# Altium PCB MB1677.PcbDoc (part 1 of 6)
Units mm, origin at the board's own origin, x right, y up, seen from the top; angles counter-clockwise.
Board outline 78 x 105 mm, 6 copper layers (Top Layer, Signal Layer 1, Signal Layer 2, Signal Layer 3, Signal Layer 4, Bottom Layer), stack 1.574 mm thick; 404 components, 325 nets, 1691 pads, 961 vias.
Unrouted connection lines stored in the file: 9.
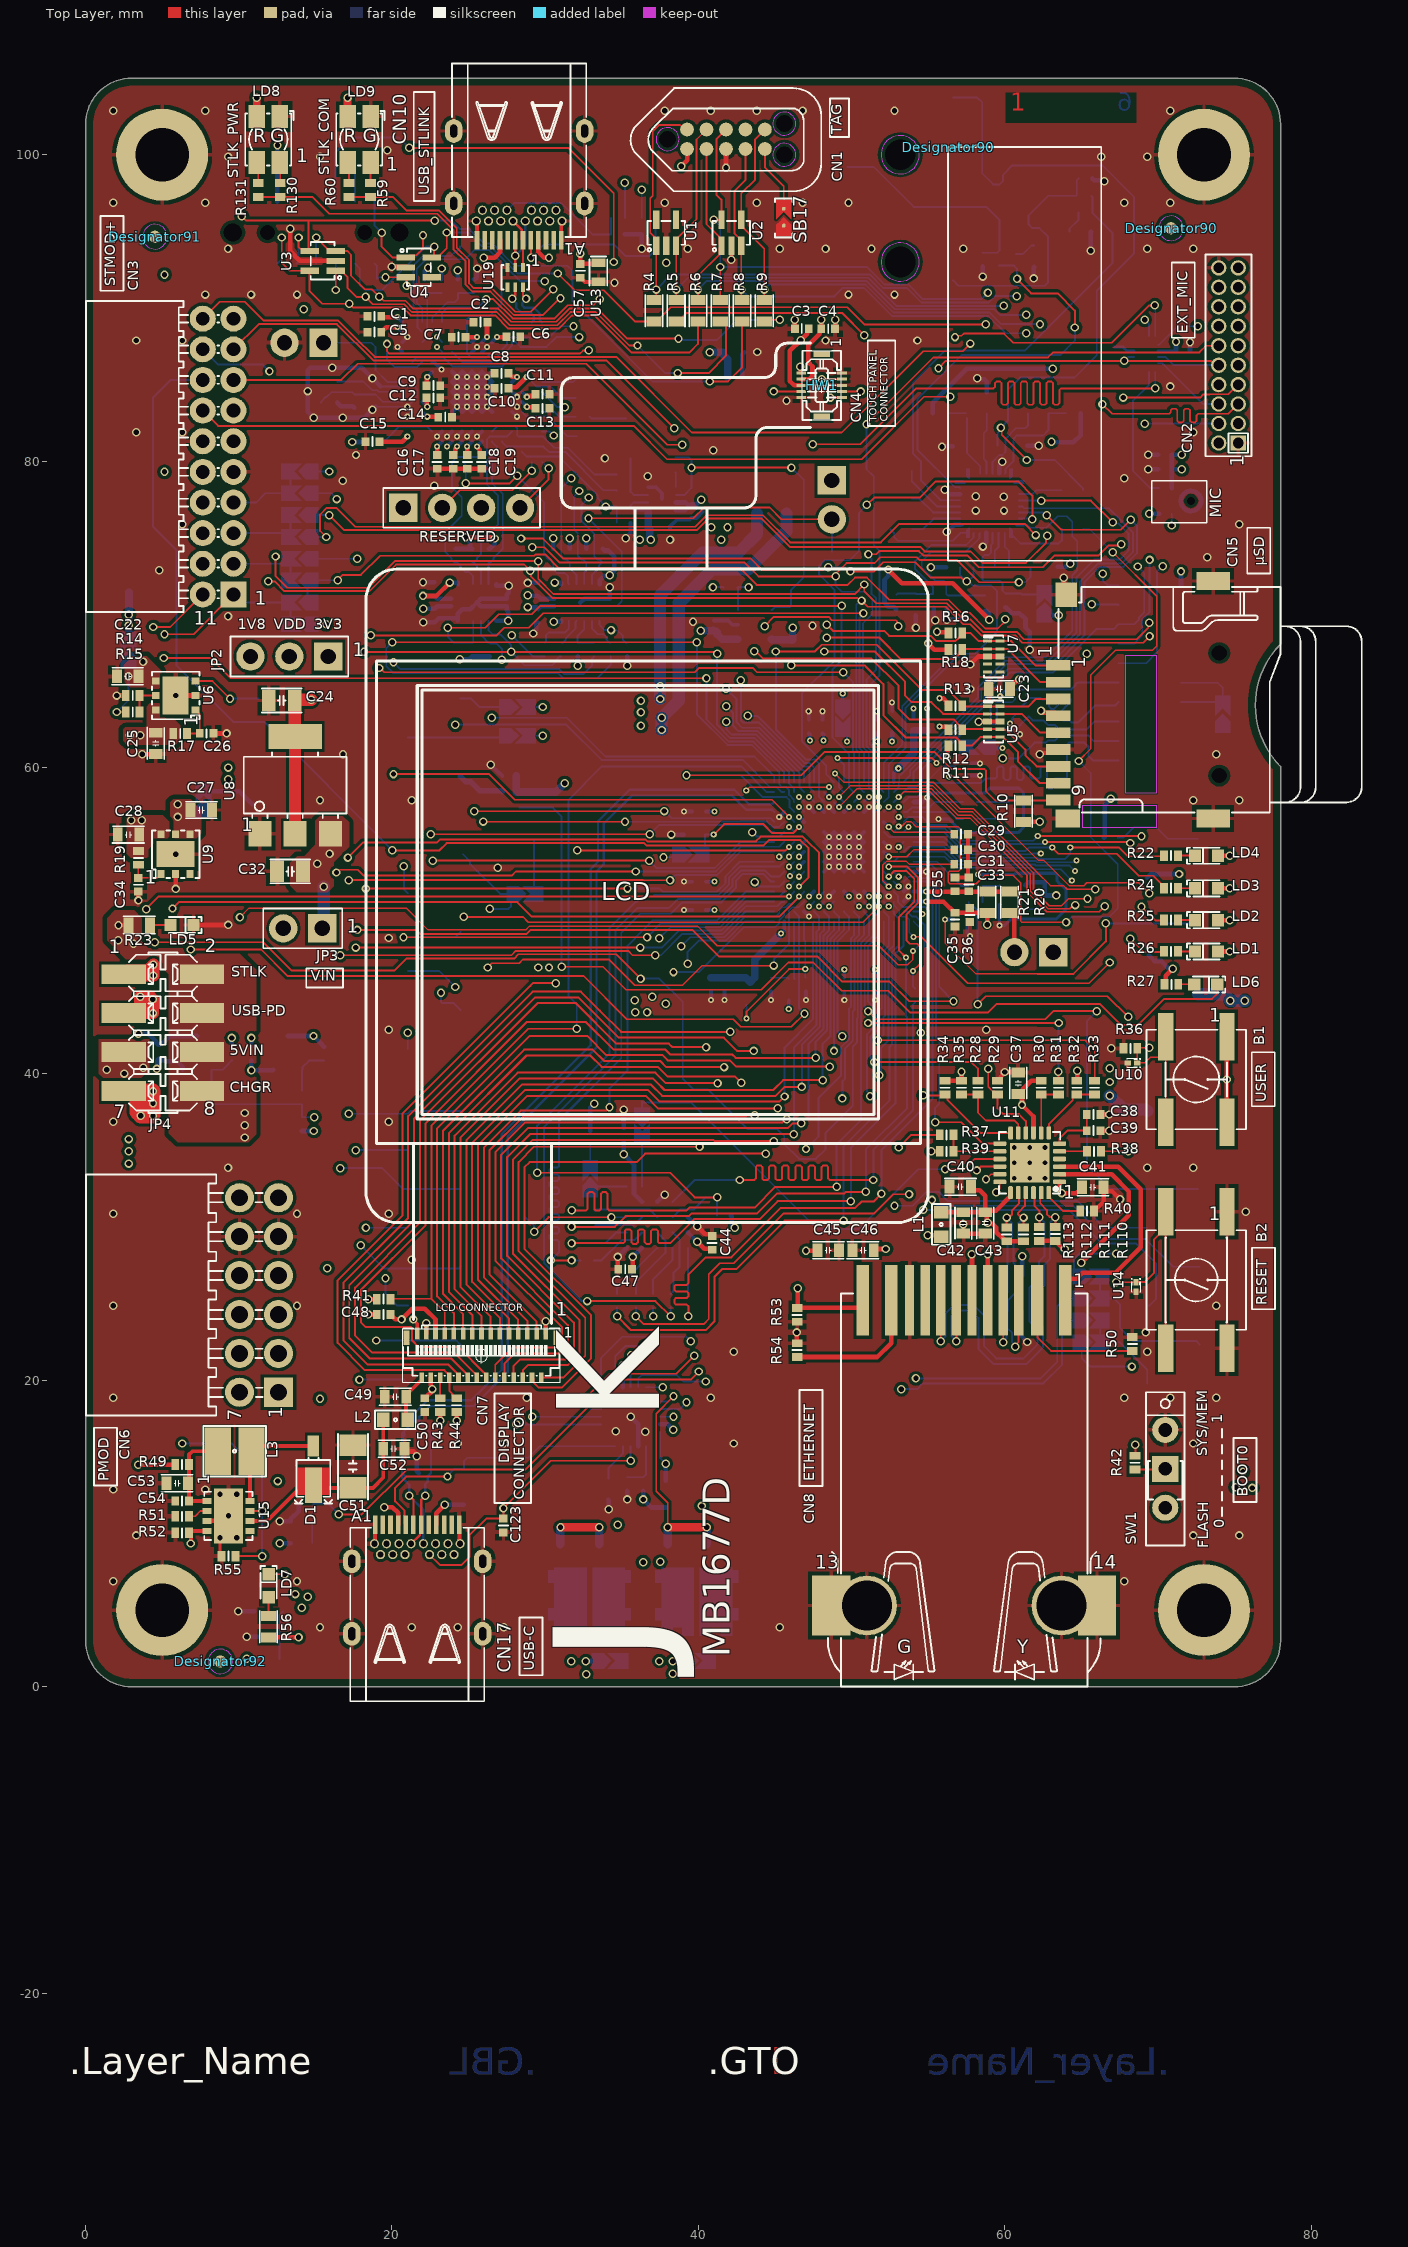
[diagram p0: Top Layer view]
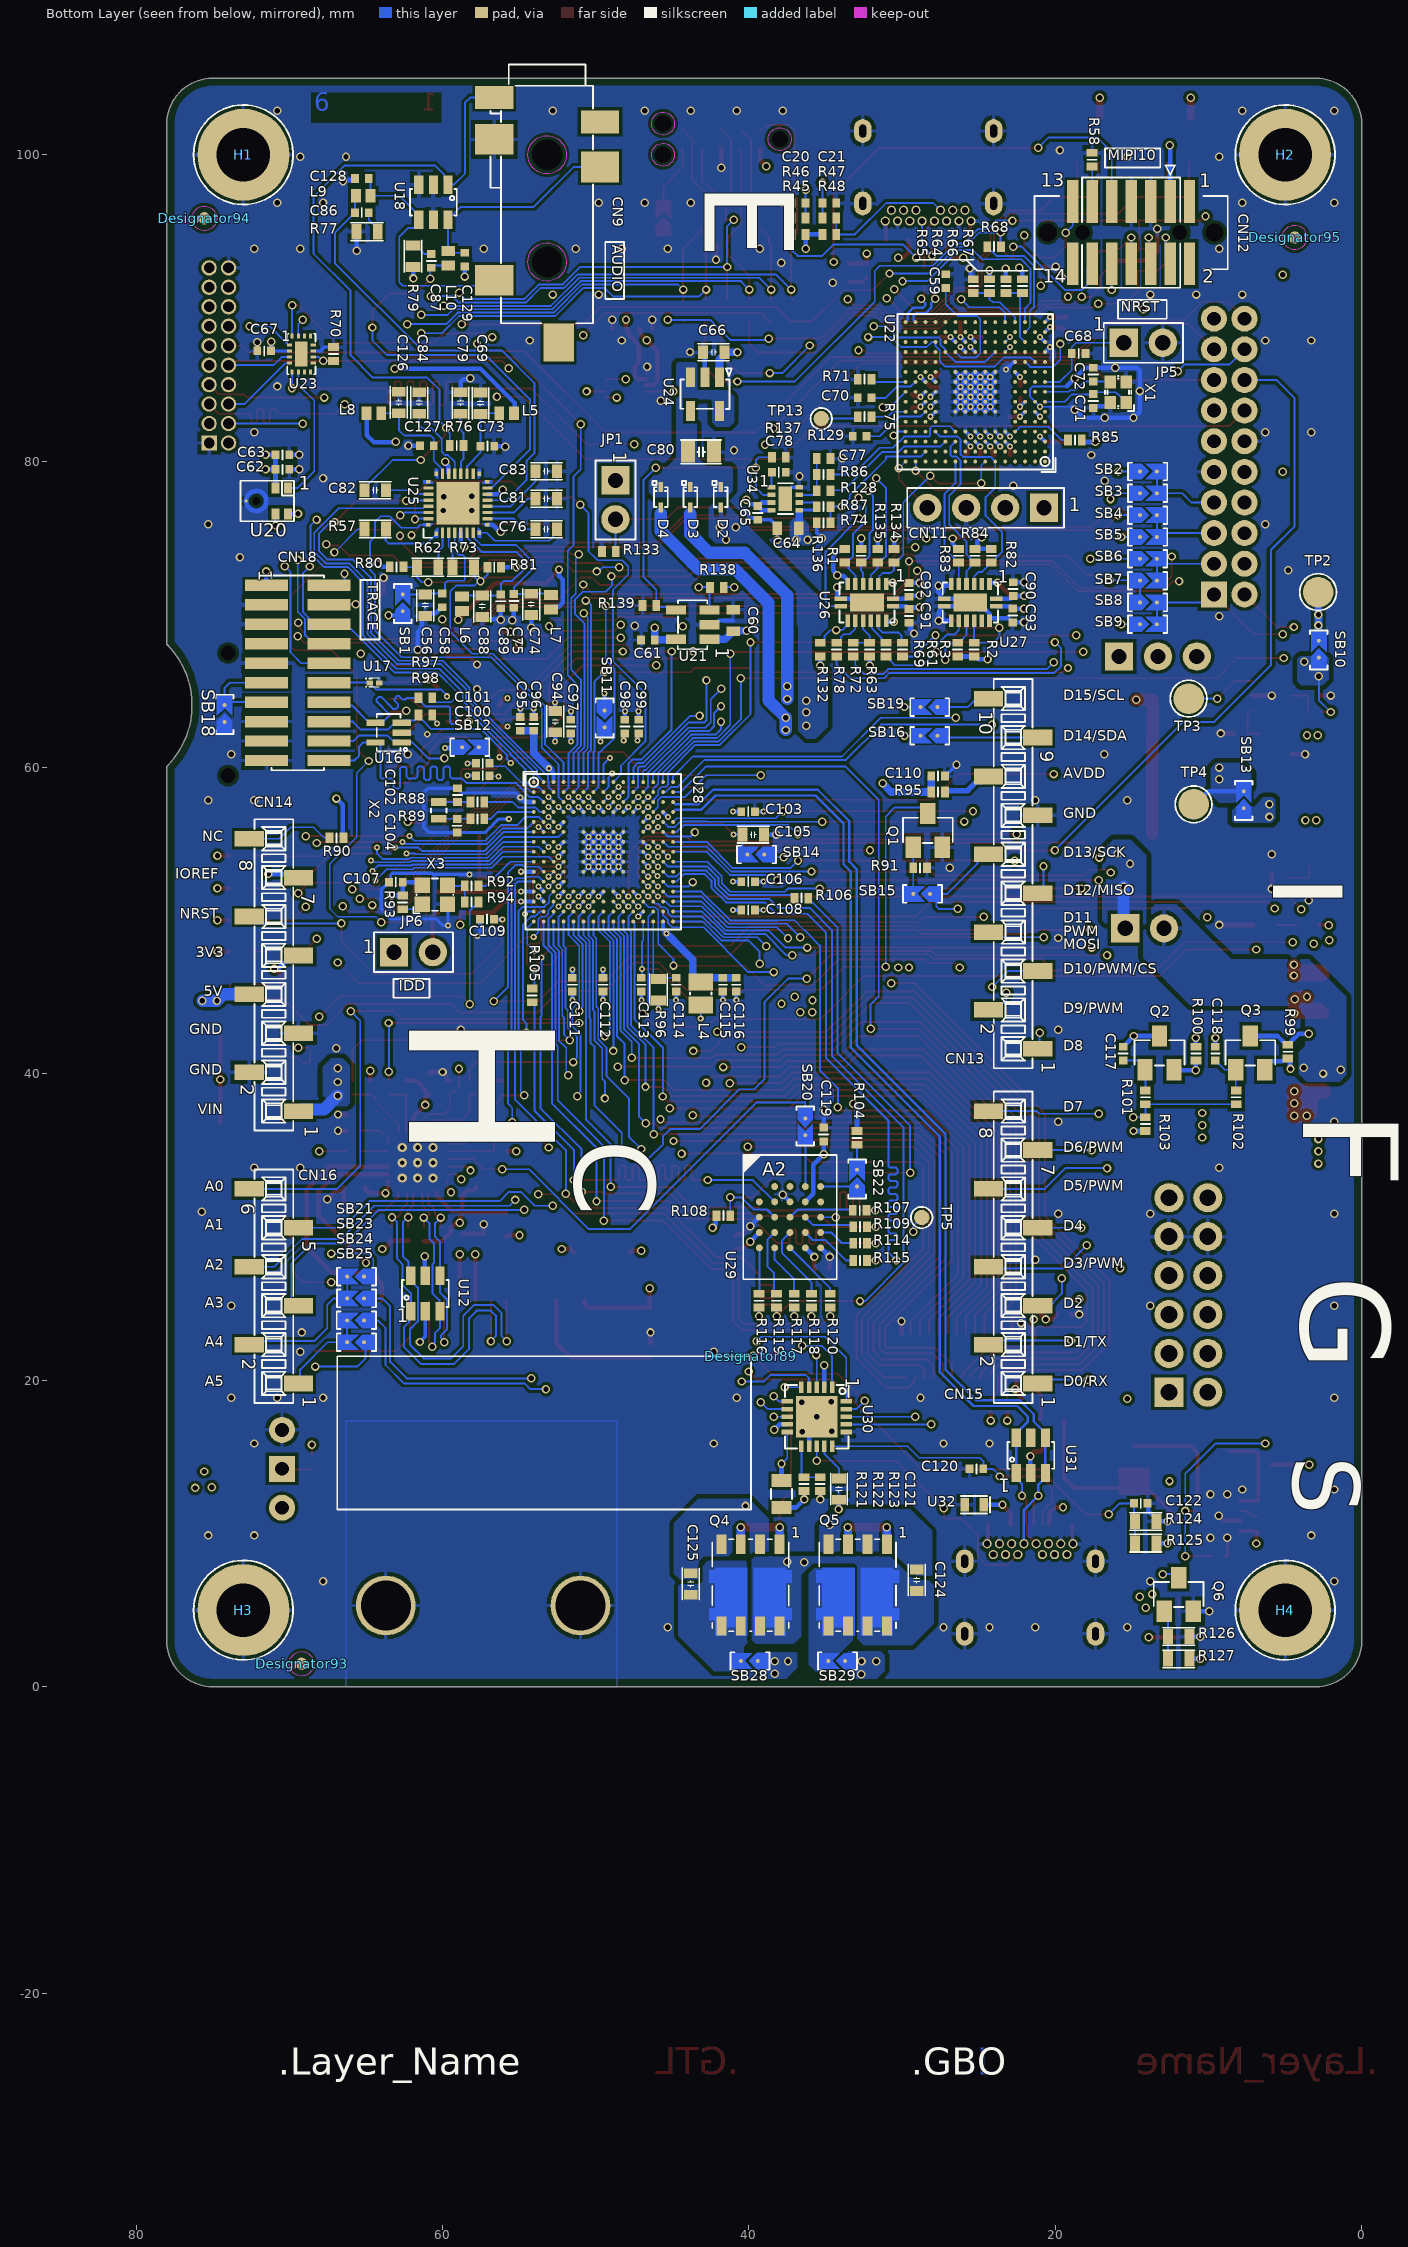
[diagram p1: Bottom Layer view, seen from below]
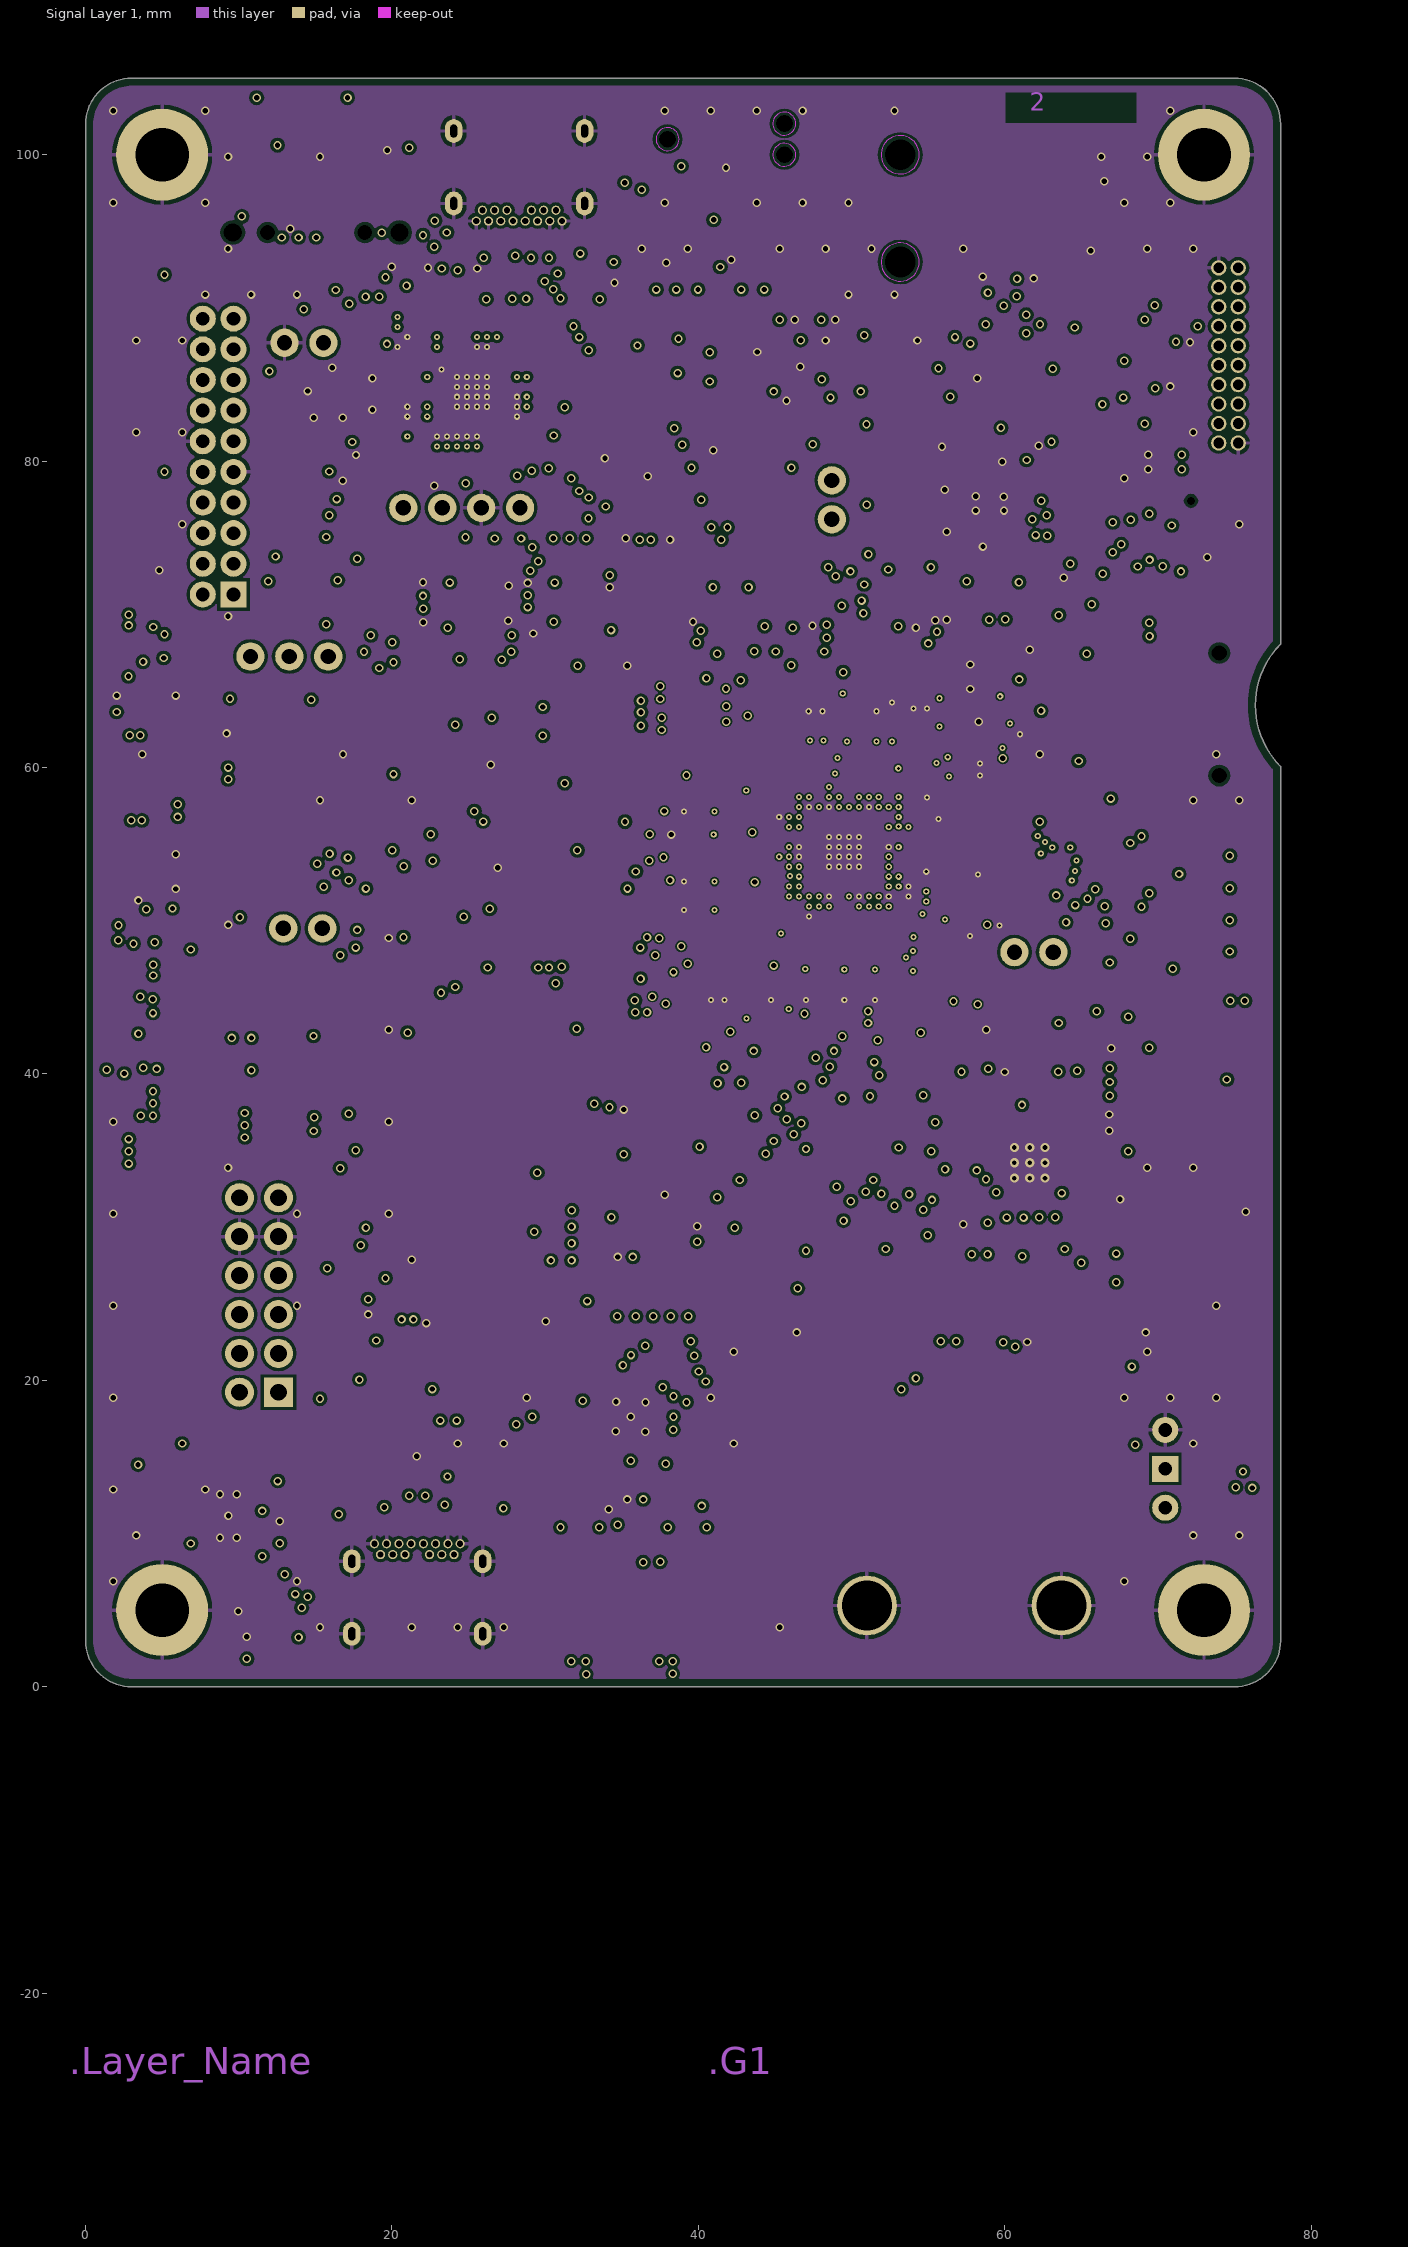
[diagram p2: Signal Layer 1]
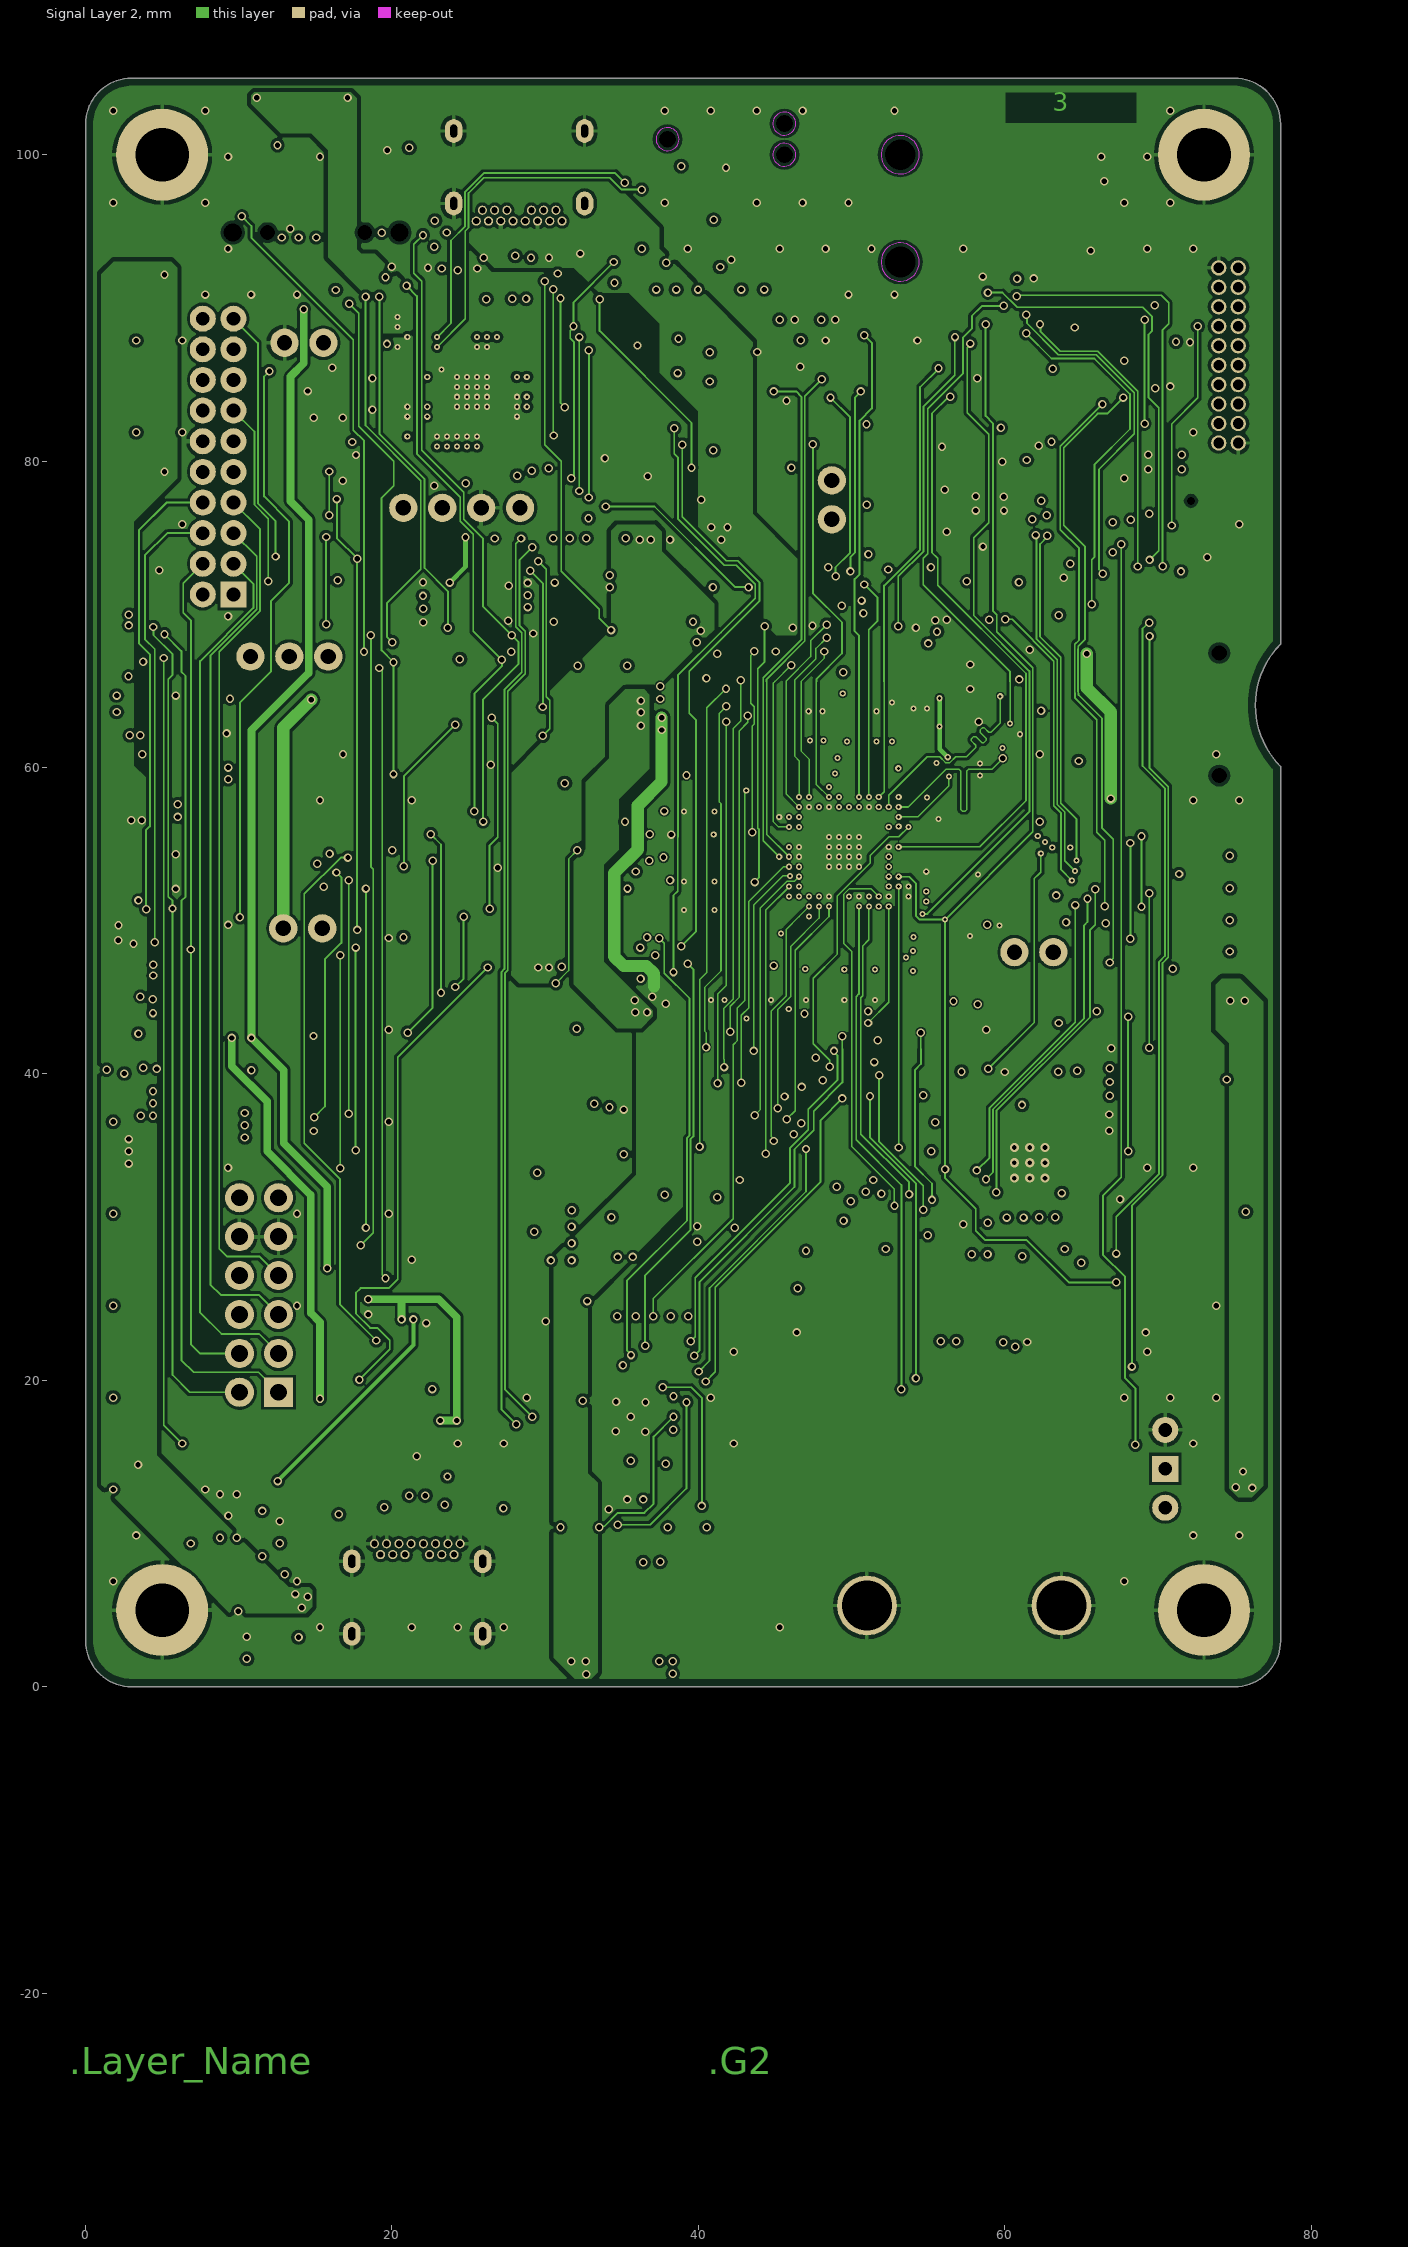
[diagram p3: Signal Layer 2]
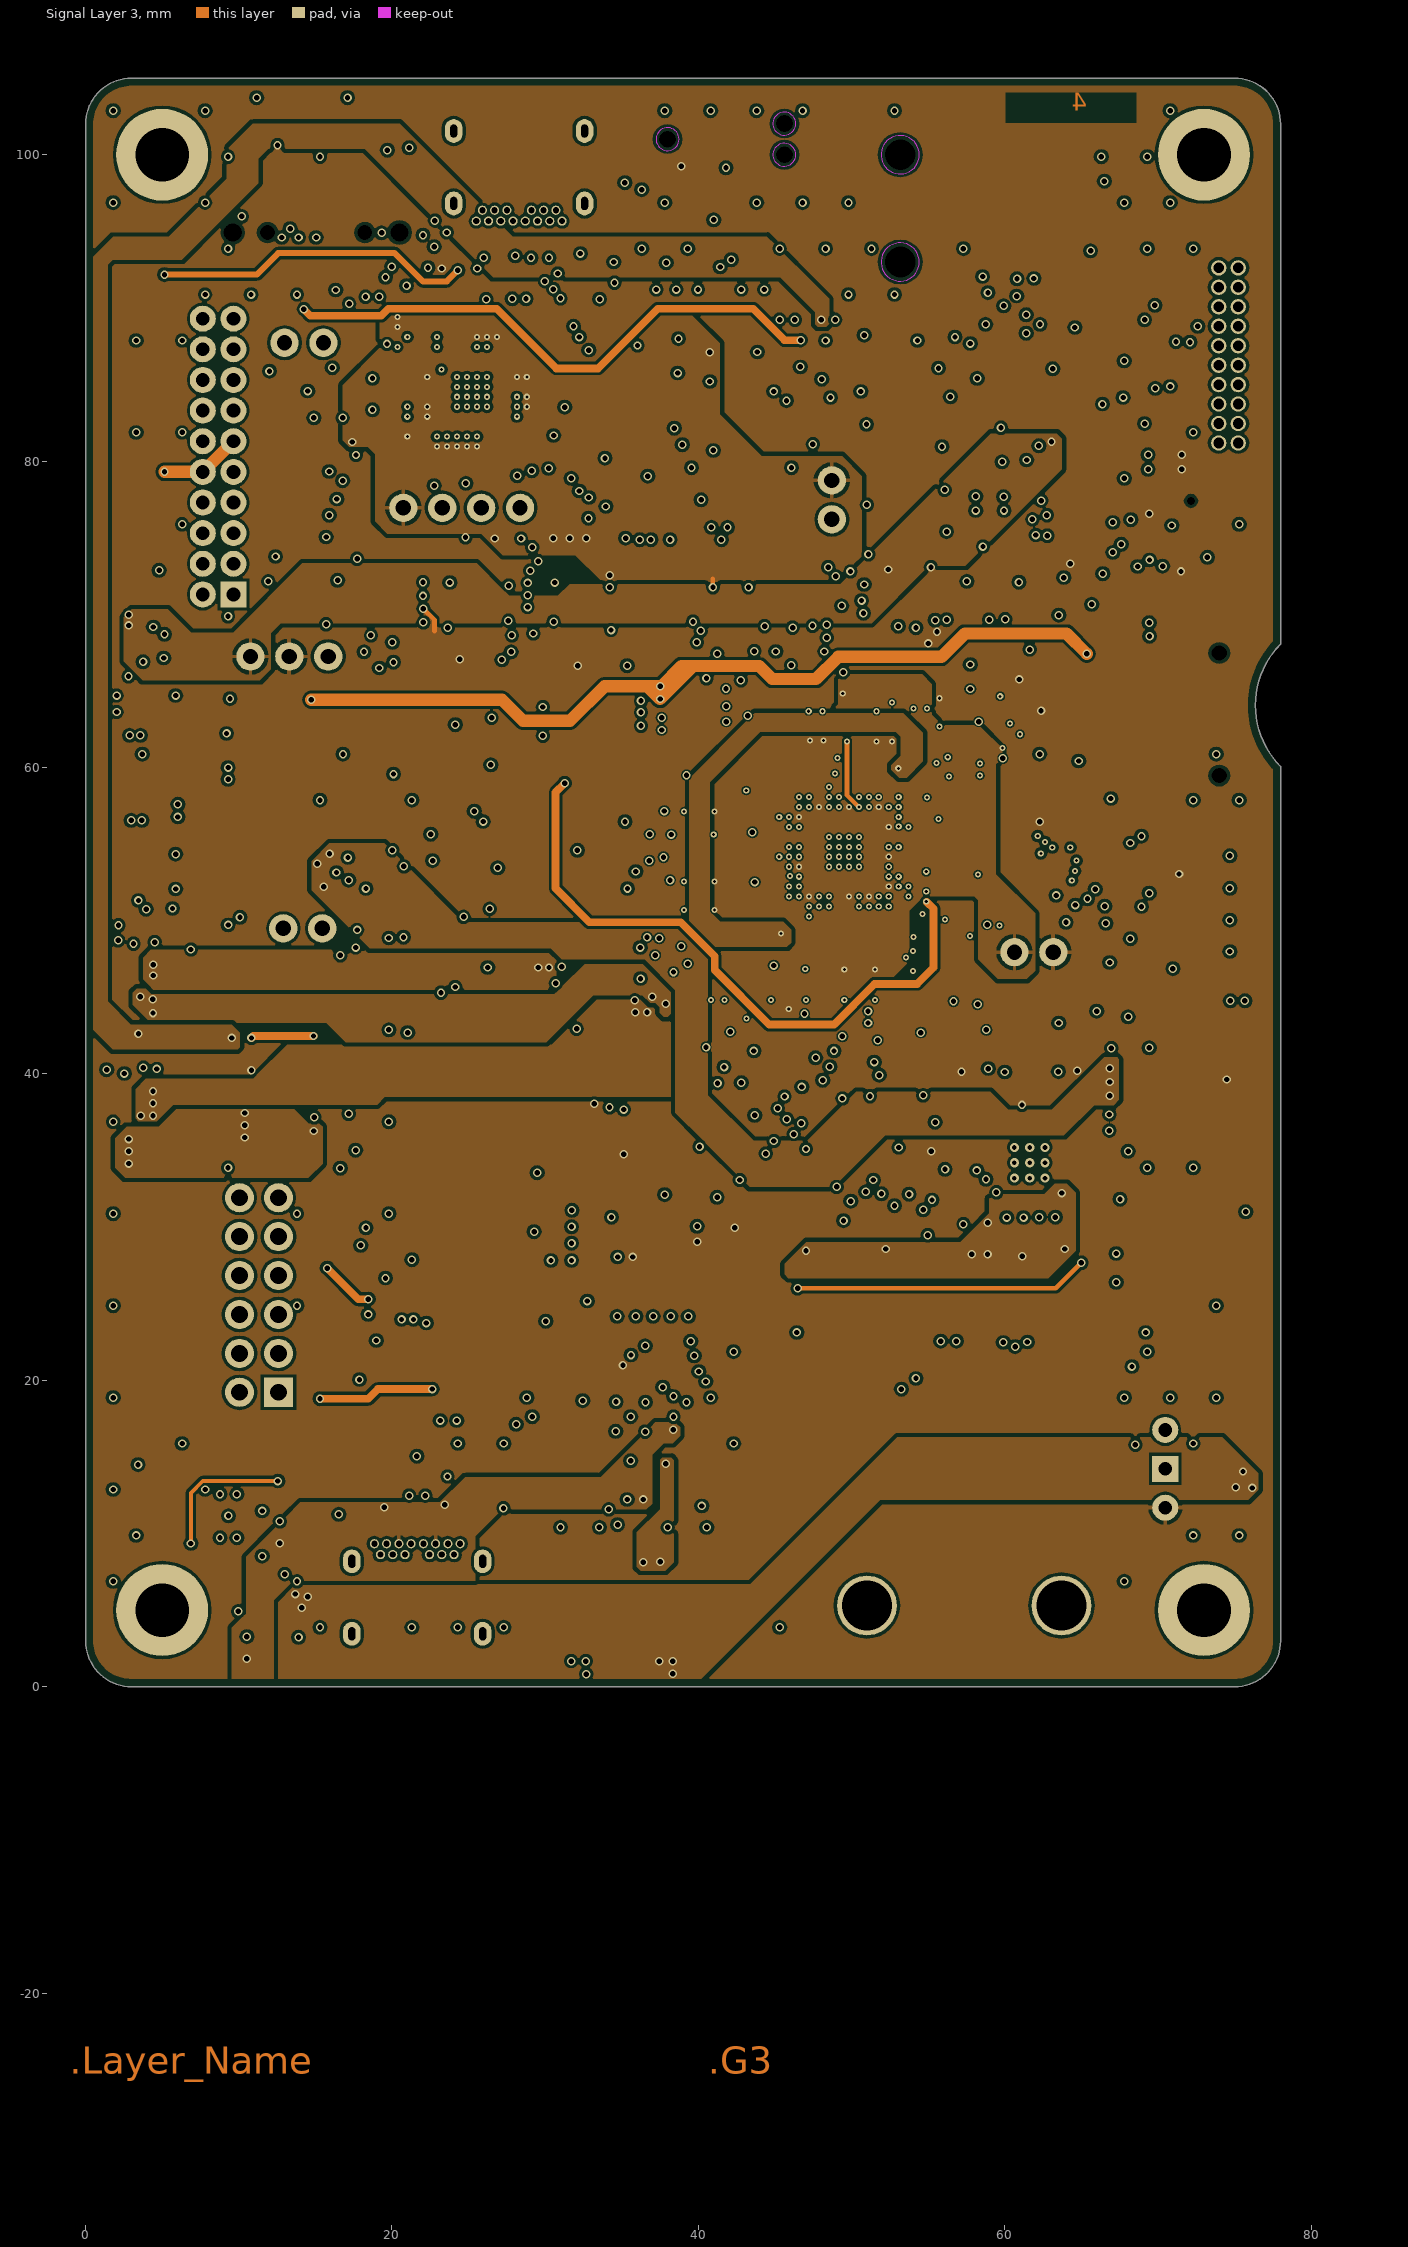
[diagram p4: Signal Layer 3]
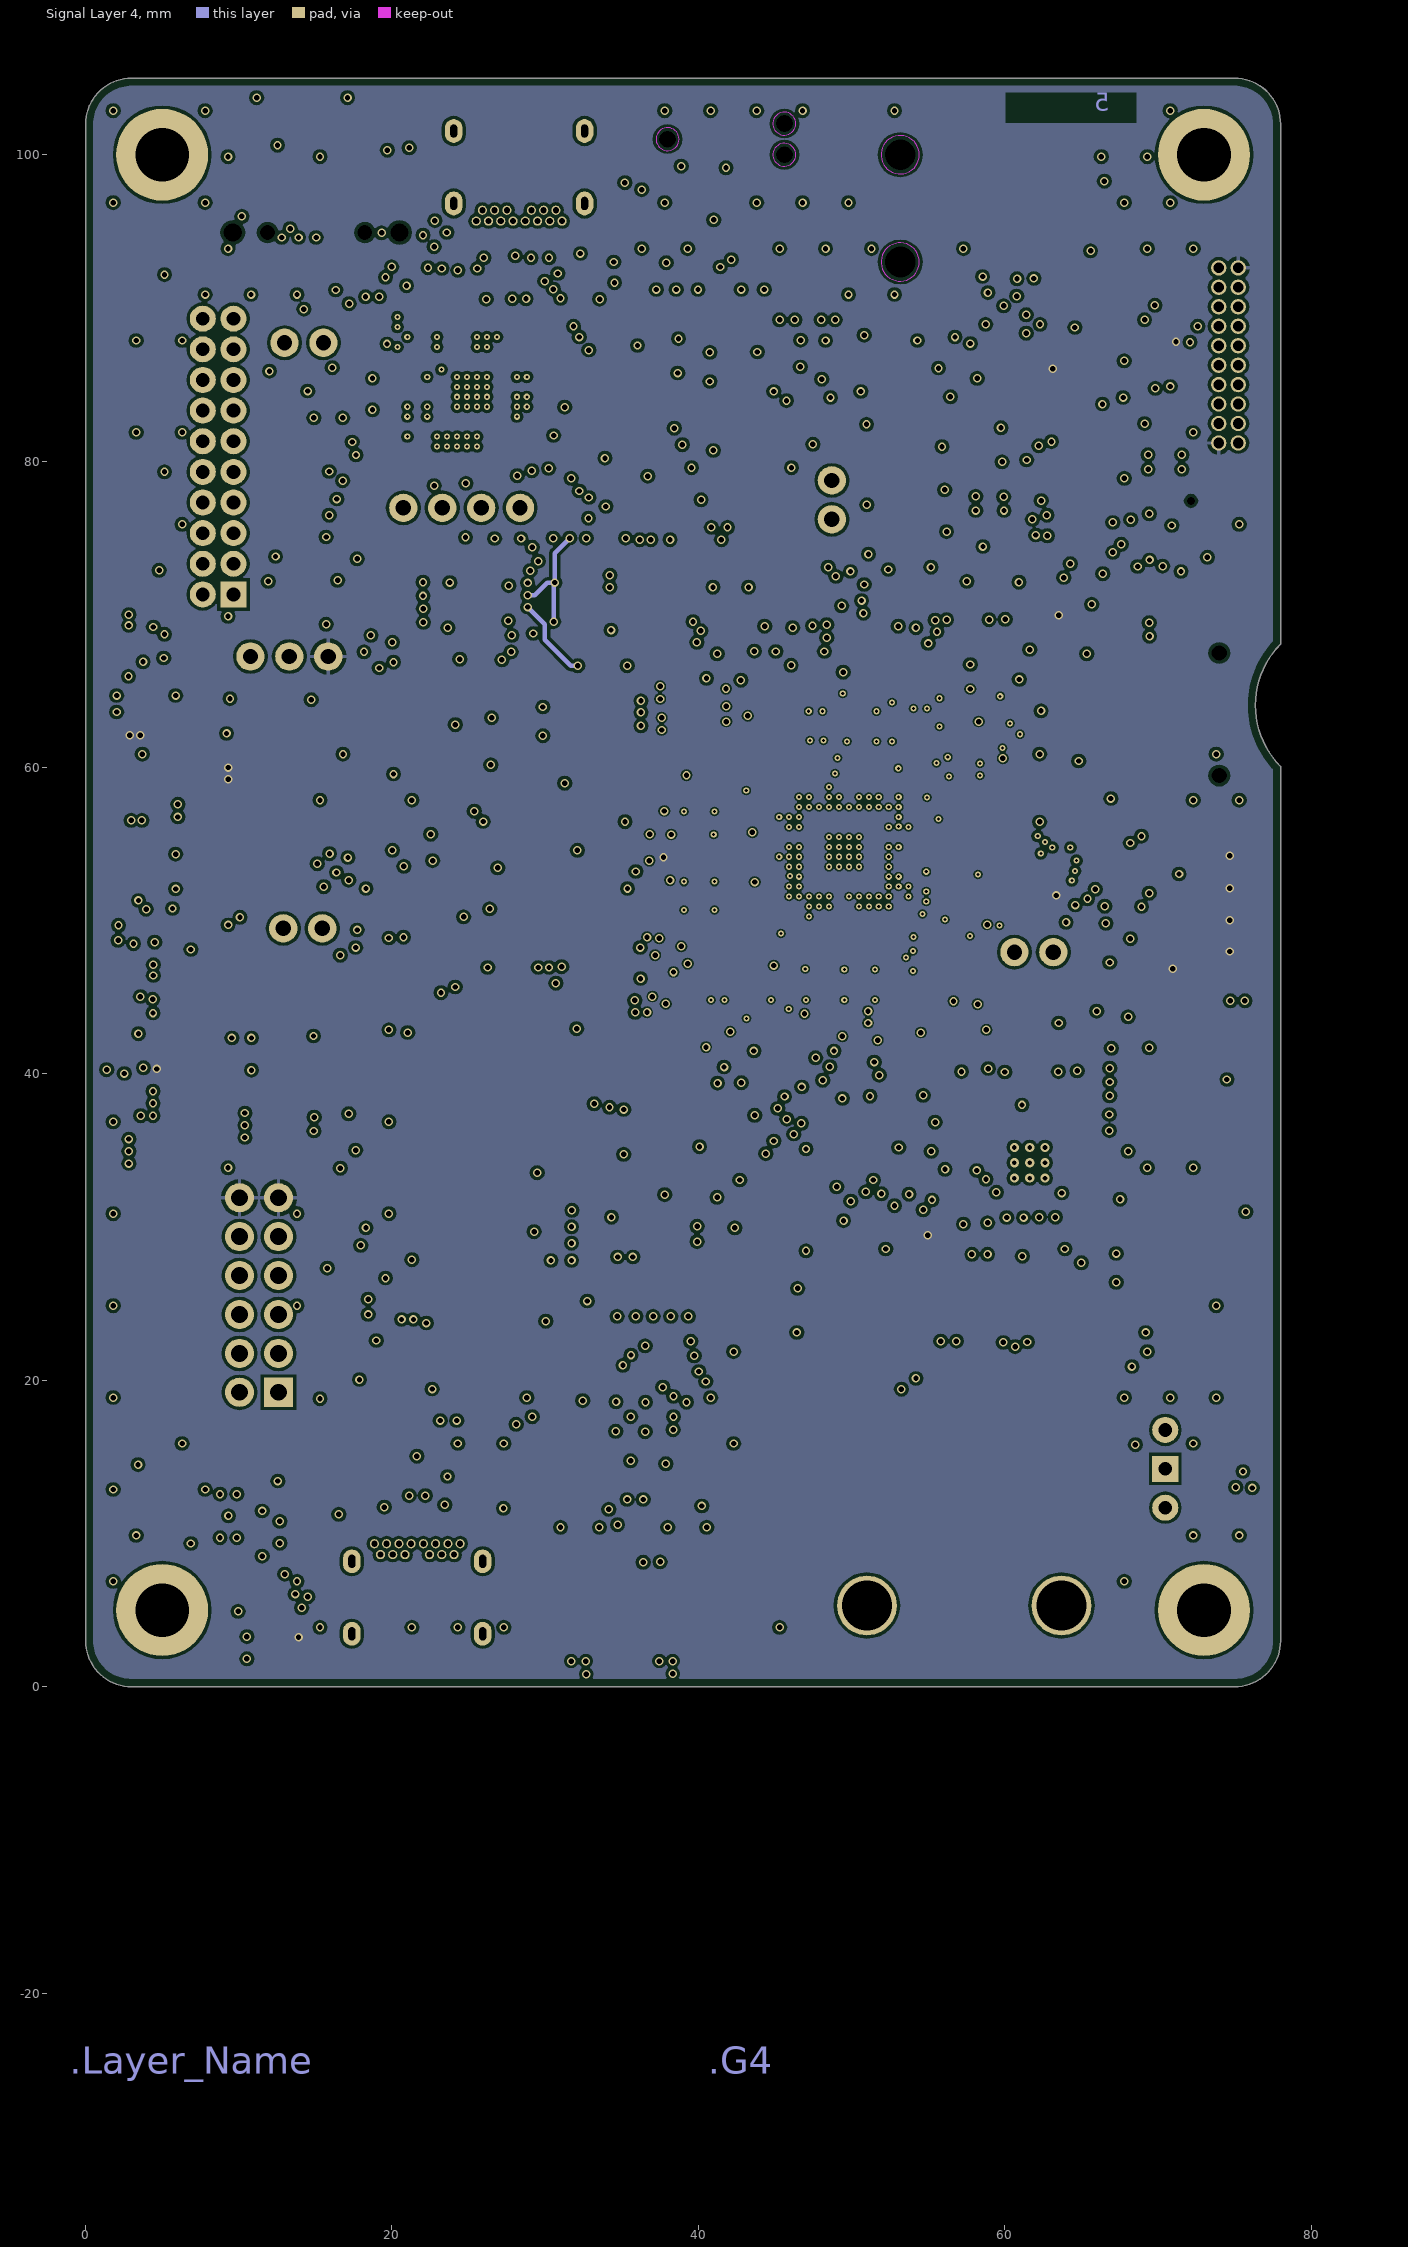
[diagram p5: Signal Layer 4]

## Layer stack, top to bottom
Top Solder: solder mask 0.015, Solder Resist, Dk 3.5
Top Layer: signal copper 0.042
Dielectric 1: prepreg 0.1, Dk 4.2
Signal Layer 1: signal copper 0.035
Dielectric 2: core 0.102, Dk 4.2
Signal Layer 2: signal copper 0.035
Dielectric 3: prepreg 0.946, Dk 4.2
Signal Layer 3: signal copper 0.035
Dielectric 4: core 0.102, Dk 4.2
Signal Layer 4: signal copper 0.035
Dielectric 5: prepreg 0.1, Dk 4.2
Bottom Layer: signal copper 0.042
Bottom Solder: solder mask 0.015, Solder Resist, Dk 3.5

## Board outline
3,0 cw(c3,3) 0,3 0,102 cw(c3,102) 3,105 75,105 cw(c75,102) 78,102 78,68.05 ccw(c82.012,64.062) 78,60.075 78,3 cw(c75,3) 75,0

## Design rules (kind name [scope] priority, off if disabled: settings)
BoardOutlineClearance [All] p1: gap=0.5 ignorepadtopadclearanceinfootprint=FALSE
Clearance Clearance_BGA-MCU [WithinRoom('RoomDefinition') And TouchesRoom('RoomDefinition')] p1: gap=0.1 ignorepadtopadclearanceinfootprint=FALSE except(0: Arc-Hole Track-Hole SMDPad-Hole THPad-Hole Via-Hole Fill-Hole Poly-Hole Region-Hole Text-Hole; 0.15: SMDPad-SMDPad; 0.2: Arc-Fill Arc-Poly Track-Fill Track-Poly SMDPad-THPad SMDPad-Fill SMDPad-Poly THPad-THPad THPad-Fill THPad-Poly Via-Via Via-Fill Fill-Poly; 0.3: Fill-Fill Poly-Poly)
Clearance Clearance_55_ohms [InNetClass('55_ohms')] p2: gap=0.1 ignorepadtopadclearanceinfootprint=FALSE except(0: Arc-Hole Track-Hole SMDPad-Hole THPad-Hole Via-Hole Fill-Hole Poly-Hole Region-Hole Text-Hole; 0.15: SMDPad-SMDPad; 0.2: Arc-Fill Arc-Poly Track-Fill Track-Poly SMDPad-THPad SMDPad-Fill SMDPad-Poly THPad-THPad THPad-Fill THPad-Poly Via-Via Via-Fill Via-Poly Fill-Poly; 0.25: Track-Track; 0.3: Fill-Fill Poly-Poly)
Clearance Clearance_Default [All] p3: gap=0.1 ignorepadtopadclearanceinfootprint=FALSE except(0: Arc-Hole Track-Hole SMDPad-Hole THPad-Hole Via-Hole Fill-Hole Poly-Hole Region-Hole Text-Hole; 0.09: Track-THPad; 0.15: SMDPad-SMDPad; 0.2: Arc-Fill Arc-Poly Track-Fill Track-Poly SMDPad-THPad SMDPad-Fill SMDPad-Poly THPad-THPad THPad-Fill THPad-Poly Via-Via Via-Fill Via-Poly Fill-Poly; 0.3: Fill-Fill Poly-Poly)
ComponentClearance [All] p1 off: gap=0.025 collisioncheckmode=3 verticalgap=0 showdistances=FALSE
DiffPairsRouting DiffPairsRouting_100_ohms [InDifferentialPairClass('Diff_100_ohms')] p1: maxlimit=0.277 minlimit=0.25 mostfreqgap=0.277 toplayer_maxgap=0.25 toplayer_prefgap=0.25 toplayer_minwidth=0.13 toplayer_maxwidth=0.13 toplayer_prefwidth=0.13 midlayer1_minwidth=0.381 midlayer1_maxwidth=0.381 midlayer1_prefwidth=0.381 midlayer2_mingap=0.277 midlayer2_minwidth=0.104 midlayer2_maxwidth=0.104 midlayer2_prefwidth=0.104 midlayer3_mingap=0.277 midlayer3_minwidth=0.104 midlayer3_maxwidth=0.104 midlayer3_prefwidth=0.104 midlayer4_minwidth=0.381 midlayer4_maxwidth=0.381 midlayer4_prefwidth=0.381 bottomlayer_maxgap=0.25 bottomlayer_prefgap=0.25 bottomlayer_minwidth=0.13 bottomlayer_maxwidth=0.13 bottomlayer_prefwidth=0.13 maxuncoupledlength=12.7
DiffPairsRouting DiffPairsRouting_90_ohms [InDifferentialPairClass('Diff_90_ohms')] p2: maxlimit=0.254 minlimit=0.226 mostfreqgap=0.251 toplayer_maxgap=0.226 toplayer_prefgap=0.226 toplayer_minwidth=0.155 toplayer_maxwidth=0.155 toplayer_prefwidth=0.155 midlayer1_minwidth=0.381 midlayer1_maxwidth=0.381 midlayer1_prefwidth=0.381 midlayer2_mingap=0.251 midlayer2_maxgap=0.251 midlayer2_minwidth=0.13 midlayer2_maxwidth=0.13 midlayer2_prefwidth=0.13 midlayer3_mingap=0.251 midlayer3_maxgap=0.251 midlayer3_minwidth=0.13 midlayer3_maxwidth=0.13 midlayer3_prefwidth=0.13 midlayer4_minwidth=0.381 midlayer4_maxwidth=0.381 midlayer4_prefwidth=0.381 bottomlayer_maxgap=0.226 bottomlayer_prefgap=0.226 bottomlayer_minwidth=0.155 bottomlayer_maxwidth=0.155 bottomlayer_prefwidth=0.155 maxuncoupledlength=12.7
HoleSize [All] p1: absolutevalues=TRUE maxlimit=10 minlimit=0.025 maxpercent=80.000 minpercent=20.000
HoleToHoleClearance [All] p1: gap=0.25 allowstackedmicrovias=TRUE
MatchedLengths MatchedLengths_OCTOSPI [InxSignalClass('OCTOSPI')] p1: tolerance=7 checknetsindiffpair=FALSE checkdiffpairvsdiffpair=TRUE checkxsignals=TRUE checkothers=TRUE
MaxMinImpedance "Schematic Impedance Constraint" [InNet('USB_DEV_HS_P')] p1: minimum=85,00 maximum=95,00
MinimumSolderMaskSliver [All] p1: minsoldermaskwidth=0
PlaneConnect [All] p1: planeconnectstyle=Relief reliefexpansion=0.508 reliefentries=4 reliefconductorwidth=0.4 reliefairgap=0.4
PolygonConnect PolygonConnect_NOFT [IsNamedPolygon('NO_FT')] p1: thpad.connectstyle=Relief thpad.reliefconductorwidth=0.25 thpad.reliefentries=4 thpad.polygonreliefangle="90 Angle" thpad.airgapwidth=0.25 smdpad.connectstyle=Direct smdpad.reliefconductorwidth=0.254 smdpad.reliefentries=4 smdpad.polygonreliefangle="45 Angle" smdpad.airgapwidth=0.254 via.connectstyle=Direct via.reliefconductorwidth=0.254 via.reliefentries=4 via.polygonreliefangle="45 Angle" via.airgapwidth=0.254
PolygonConnect [All] p2: thpad.connectstyle=Relief thpad.reliefconductorwidth=0.25 thpad.reliefentries=4 thpad.polygonreliefangle="90 Angle" thpad.airgapwidth=0.25 smdpad.connectstyle=Relief smdpad.reliefconductorwidth=0.25 smdpad.reliefentries=4 smdpad.polygonreliefangle="90 Angle" smdpad.airgapwidth=0.25 via.connectstyle=Direct via.reliefconductorwidth=0.254 via.reliefentries=4 via.polygonreliefangle="45 Angle" via.airgapwidth=0.254
RoomDefinition [InComponentClass('Room Definition')] p1: confinementstyle=ConfineIn formatcopy=TRUE lockcomponents=FALSE outline 62.125,41.625 62.125,65.625 36.4,65.625 36.4,41.625
RoutingLayers RoutingLayers_Default [All] p1: top layer_v5=TRUE mid layer 1_v5=TRUE mid layer 2_v5=TRUE mid layer 3_v5=TRUE mid layer 4_v5=TRUE bottom layer_v5=TRUE
RoutingPriority RoutingPriority_ALL [All] p1: routingpriority=1
RoutingVias RoutingVias_Default [All] p1: holewidth=0.35 width=0.55 viastyle="Through Hole" minholewidth=0.2 minwidth=0.4 maxholewidth=0.35 maxwidth=0.6
SilkToSilkClearance [All] p1: silktosilkclearance=0
SilkToSolderMaskClearance [IsPad] p1: minsilkscreentomaskgap=0 clearancetoexposedcopper=TRUE
SolderMaskExpansion [All] p1: expansion=0.102 istentingtop=FALSE
Width Width_BGA-MCU [WithinRoom('RoomDefinition') And TouchesRoom('RoomDefinition')] p1: maxlimit=1 minlimit=0.1 preferedwidth=0.1 minimp=50.000000 maximp=50.000000 favimp=50.000000
Width Width_55_ohms [InNetClass('55_ohms')] p2: maxlimit=0.254 minlimit=0.1 preferedwidth=0.254 toplayer_minwidth=0.13 toplayer_maxwidth=0.13 toplayer_prefwidth=0.13 midlayer2_maxwidth=0.1 midlayer2_prefwidth=0.1 midlayer3_maxwidth=0.1 midlayer3_prefwidth=0.1 bottomlayer_minwidth=0.13 bottomlayer_maxwidth=0.13 bottomlayer_prefwidth=0.13 minimp=50.000000 maximp=50.000000 favimp=50.000000
Width Width_Alim [InNetClass('ALIM')] p3: maxlimit=1 minlimit=0.1 preferedwidth=0.3
Width Width_Default [All] p4: maxlimit=1 minlimit=0.09 preferedwidth=0.12 minimp=50.000000 maximp=50.000000 favimp=50.000000
20 further rules are at their usual default settings.

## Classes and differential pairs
component class U_microSDcard: C23 CN5 R10 R11 R12 R13 R16 R18 U5 U7
net class TRACE: TRACECLK TRACED0 TRACED1 TRACED2 TRACED3
net class ALIM: 1V8 3V3 3V3_LCD 3V3_STLK 5V 5V_UCPD 5V_VIN GND VBUSC VDD VDD_LCD VDD_MCU VDDA VIN VREFP
differential pair class Diff_100_ohms: RD RX TD TX
differential pair class Diff_90_ohms: STLK_USB STLK_USB_CN USB_DEV_HS USB_DEV_HS_CN USB_FS
net class 55_ohms: LCD_A0_RS LCD_D0 LCD_D1 LCD_D2 LCD_D3 LCD_D4 LCD_D5 LCD_D6 LCD_D7 LCD_D8 LCD_D9 LCD_D10 LCD_D11 LCD_D12 LCD_D13 LCD_D14 LCD_D15 LCD_NE1_CS LCD_NOE LCD_NWE NetR105_2 NetR107_2 NetR114_1 NetR115_1 NetR116_1 NetR117_1 NetR119_1 NetR120_1 OCSPI1_CLK OCSPI1_DQS OCSPI1_IO0 OCSPI1_IO1 OCSPI1_IO2 OCSPI1_IO3 OCSPI1_IO4 OCSPI1_IO5 OCSPI1_IO6 OCSPI1_IO7 OCSPI1_NCS SDIO1_CK SDIO1_CMD SDIO1_D0 SDIO1_D1 SDIO1_D2 SDIO1_D3 TRACECLK TRACED0 TRACED1 TRACED2 TRACED3
net class OCTOSPI: NetR105_2 NetR107_2 NetR109_1 NetR114_1 NetR115_1 NetR116_1 NetR117_1 NetR118_2 NetR119_1 NetR120_1 OCSPI1_CLK OCSPI1_DQS OCSPI1_IO0 OCSPI1_IO1 OCSPI1_IO2 OCSPI1_IO3 OCSPI1_IO4 OCSPI1_IO5 OCSPI1_IO6 OCSPI1_IO7 OCSPI1_NCS
component class U_Arduino: C110 CN13 CN14 CN15 CN16 LD6 Q1 R27 R90 R91 R95 SB15 SB16 SB19 SB21 SB23 SB24 SB25
component class U_Audio_Codec: C56 C58 C62 C63 C67 C69 C73 C74 C75 C76 C79 C81 C82 C83 C84 C86 C87 C88 C89 C126 C127 C128 C129 CN2 CN9 L5 L6 L7 L8 L9 L10 R57 R62 R70 R73 R76 R77 R79 R80 R81 SB1 U18 U20 U23 U25
component class U_Ethernet: C37 C38 C39 C40 C41 C42 C43 C45 C46 CN8 L1 R28 R29 R30 R31 R32 R33 R34 R35 R37 R38 R39 R40 R50 R53 R54 R110 R111 R112 R113 U11 U12
component class U_JTAG: CN1 CN18 R4 R5 R6 R7 R8 R9 R97 R98 SB17 SB18 U1 U2 U16 U17
component class U_LCD: C3 C4 C48 C49 C50 C51 C52 C53 C54 C117 C118 CN4 CN7 D1 H1 H2 H3 H4 HW1 L2 L3 Q2 Q3 R41 R43 R44 R49 R51 R52 R55 R99 R100 R101 R102 R103 U15
component class U_STM32_microcontroller_IOs: B2 C102 C104 C107 C109 R42 R88 R89 R92 R93 R94 R105 R106 R107 R109 R114 R115 R116 R117 R118 R119 R120 SW1 U14 U28 X2 X3
component class "U_NOR Flash memory": C44 C47 C119 R104 R108 SB20 SB22 TP5 U29
component class U_Peripherals: B1 C101 CN3 CN6 LD1 LD2 LD3 LD4 R22 R24 R25 R26 R36 SB2 SB3 SB4 SB5 SB6 SB7 SB8 SB9 U10
component class U_Board_power: C22 C24 C25 C26 C27 C28 C32 C34 HW2 JP2 JP3 JP4 LD5 R14 R15 R17 R19 R23 SB10 SB13 TP2 TP3 TP4 U6 U8 U9
component class U_STM32_microcontroller_power: C29 C30 C31 C33 C35 C36 C55 C94 C95 C96 C97 C98 C99 C100 C103 C105 C106 C108 C111 C112 C113 C114 C115 C116 HW3 JP6 L4 R20 R21 R96 SB11 SB12 SB14
component class U_STLINK_V3EC: C1 C2 C5 C6 C7 C8 C9 C10 C11 C12 C13 C14 C15 C16 C17 C18 C19 C20 C21 C57 C59 C60 C61 C64 C65 C66 C68 C70 C71 C72 C77 C78 C80 C90 C91 C92 C93 CN10 CN11 CN12 D2 D3 D4 JP1 JP5 LD8 LD9 R1 R2 R3 R45 R46 R47 R48 R58 R59 R60 R61 R63 R64 R65 R66 R67 R68 R69 R71 R72 R74 R75 R78 R82 R83 R84 R85 R86 R87 R128 R129 R130 R131 R132 R133 R134 R135 R136 R137 R138 R139 TP13 U3 U4 U13 U19 U21 U22 U24 U26 U27 U34 X1
component class U_USB-PD: C120 C121 C122 C123 C124 C125 CN17 LD7 Q4 Q5 Q6 R56 R121 R122 R123 R124 R125 R126 R127 SB28 SB29 U30 U31 U32
differential pair RD: +RD_P -RD_N
differential pair TD: +TD_P -TD_N
differential pair RX: +"" -""
differential pair TX: +"" -""
differential pair USB_FS: +USB_FS_P -USB_FS_N
differential pair STLK_USB_CN: +STLK_USB_CN_P -STLK_USB_CN_N
differential pair STLK_USB: +STLK_USB_P -STLK_USB_N

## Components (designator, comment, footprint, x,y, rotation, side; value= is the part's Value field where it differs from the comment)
B1 "SW_BLUE_KSC721JLFS" SWI_C&K_KSC721JLFS_BLUE 72.5,39.637 r270 top value=KSC721JLFS
B2 "SW_BLACK_KSC321GLFS" SWI_C&K_KSC321GLFS_BLACK 72.5,26.55 r270 top value=KSC321GLFS
C1 "Capacitor" C0402 18.85,89.45 r180 top value=100nF
C2 "Capacitor" C0402 25.775,89.075 r180 top value=100nF
C3 "Capacitor" C0402 46.75,88.65 r0 top value=100nF
C4 "Capacitor" C0402 48.475,88.65 r180 top value=100nF
C5 "Capacitor" C0402 18.85,88.425 r180 top value=100nF
C6 "Capacitor" C0402 27.925,88.125 r0 top value=100nF
C7 "Capacitor" C0402 24.35,88.1 r180 top value=100nF
C8 "Capacitor" C0402 27.15,85.725 r180 top value=100nF
C9 "Capacitor" C0402 22.7,84.925 r0 top value=100nF
C10 "Capacitor" C0402 27.15,84.75 r180 top value=100nF
C11 "Capacitor" C0402 29.825,84.375 r0 top value=100nF
C12 "Capacitor" C0402 22.7,84.125 r0 top value=100nF
C13 "Capacitor" C0402 29.825,83.45 r0 top value=100nF
C14 "Capacitor" C0402 23.475,82.875 r0 top value=100nF
C15 "Capacitor" C0402 18.725,81.275 r180 top value=100nF
C16 "Capacitor" C0402 22.95,79.95 r270 top value=100nF
C17 "Capacitor" C0402 24,79.95 r270 top value=100nF
C18 "Capacitor" C0402 24.925,79.95 r270 top value=100nF
C19 "Capacitor" C0402 25.85,79.95 r270 top value=100nF
C20 "Capacitor" C0402 36.75,96.85 r0 bottom value=10nF
C21 "Capacitor" C0402 34.75,96.85 r180 bottom value=10nF
C22 "Capacitor" C0603 2.75,65.95 r0 top value=4.7uF
C23 "Capacitor" C0603_H0P8 59.65,65.125 r180 top value=4.7uF
C24 "Capacitor" C0805 12.8,64.375 r0 top value=10uF
C25 "Capacitor" C0603 4.575,61.575 r270 top value=4.7uF
C26 "Capacitor" C0402 7.9,62.225 r180 top value=100nF
C27 "Capacitor" C0603 7.55,57.225 r180 top value=4.7uF
C28 "Capacitor" C0603 2.8,55.625 r0 top value=4.7uF
C29 "Capacitor" C0402 57.15,55.65 r0 top value=100nF
C30 "Capacitor" C0402 57.15,54.625 r0 top value=100nF
C31 "Capacitor" C0402 57.15,53.7 r0 top value=100nF
C32 "Capacitor" C0805 13.35,53.225 r0 top value=10uF
C33 "Capacitor" C0402 57.65,52.375 r270 top value=1uF
C34 "Capacitor" C0402 3.45,52.35 r90 top value=100nF
C35 "Capacitor" C0402 56.75,50.075 r90 top value=100nF
C36 "Capacitor" C0402 57.725,50.375 r90 top value=1uF
C37 "Capacitor" C0603 60.875,39.4 r270 top value=100nF
C38 "Capacitor" C0402 65.8,37.35 r180 top value=1uF
C39 "Capacitor" C0402 65.8,36.3 r180 top value=470pF
C40 "Capacitor" C0603 57.1,32.625 r180 top value=100nF
C41 "Capacitor" C0603 65.75,32.6 r180 top value=100nF
C42 "Capacitor" C0603 57.3,30.275 r90 top value=100nF
C43 "Capacitor" C0603 58.725,30.275 r90 top value=10uF
C44 "Capacitor" C0402 40.9,28.975 r270 top value=100nF
C45 "Capacitor" C0603 48.475,28.5 r180 top value=100nF
C46 "Capacitor" C0603 50.75,28.5 r0 top value=100nF
C47 "Capacitor" C0402 35.225,27.25 r0 top value=100nF
C48 "Capacitor" C0402 19.45,24.3 r180 top value=100nF
C49 "Capacitor" C0603 20.225,18.925 r0 top value=100nF
C50 "Capacitor" C0402 22.15,18.375 r270 top value=100nF
C51 "Capacitor" C1206_H1P25 17.45,14.375 r270 top value=4.7uF
C52 "Capacitor" C0603 20.125,15.525 r180 top value=100nF
C53 "Capacitor" C0603 5.975,13.275 r0 top value=10uF
C54 "Capacitor" C0402 6.3,12.125 r180 top value=100nF
C55 "Capacitor" C0402 56.75,52.375 r270 top value=100nF
C56 "Capacitor" C0603 61.125,70.59 r90 bottom value=4.7uF
C57 "Capacitor" C0402 32.3,92.425 r270 top value=100pF
C58 "Capacitor" C0402 60.025,70.91 r90 bottom value=100nF
C59 "Capacitor" C0402 27.15,91.75 r270 bottom value=2.2uF
C60 "Capacitor" C0603 41.025,69.6 r270 bottom value=10uF
C61 "Capacitor" C0402 46.6,68.325 r180 bottom value=100nF
C62 "Capacitor" C0402 70.453,79.463 r180 bottom value=1uF
C63 "Capacitor" C0402 70.453,80.413 r0 bottom value=100nF
C64 "Capacitor" C0603 37.45,75.625 r180 bottom value=10uF
C65 "Capacitor" C0402 39.425,76.625 r90 bottom value=100nF
C66 "Capacitor" C0603 42.3,87.1 r180 bottom value=10uF
C67 "Capacitor" C0402 71.641,87.194 r180 bottom value=1uF
C68 "Capacitor" C0402 18.475,87.025 r0 bottom value=100nF
C69 "Capacitor" C0603 57.525,83.775 r270 bottom value=4.7uF
C70 "Capacitor" C0402 32.45,84.125 r180 bottom value=2.2uF
C71 "Capacitor" C0402 17.525,83.925 r90 bottom value=2.7pF
C72 "Capacitor" C0402 17.525,85.65 r90 bottom value=2.7pF
C73 "Capacitor" C0402 57.075,80.975 r0 bottom value=100nF
C74 "Capacitor" C0603 54.2,70.65 r90 bottom value=4.7uF
C75 "MCD-00006" C0402 55.35,70.875 r90 bottom value=100nF
C76 "Capacitor" C0603 53.225,75.55 r0 bottom value=2.2uF
C77 "Capacitor" C0402 32.775,81.625 r180 bottom value=2.2uF
C78 "Capacitor" C0402 38.05,79.275 r0 bottom value=10nF
C79 "Capacitor" C0603 58.825,83.8 r90 bottom value=4.7uF
C80 "Capacitor" C0805 43.125,80.6 r0 bottom value=2.2uF
C81 "Capacitor" C0603 53.225,77.55 r0 bottom value=2.2uF
C82 "Capacitor" C0603 64.4,78.1 r0 bottom value=1uF
C83 "Capacitor" C0603 53.225,79.35 r0 bottom value=2.2uF
C84 "Capacitor" C0603 61.525,83.8 r270 bottom value=4.7uF
C86 "Capacitor" C0402 65.27,96.225 r0 bottom value=100nF
C87 "Capacitor" C0402 60.725,93.075 r270 bottom value=100nF
C88 "Capacitor" C0603 57.4,70.525 r90 bottom value=4.7uF
C89 "Capacitor" C0402 56.2,70.85 r90 bottom value=100nF
C90 "Capacitor" C0402 22.75,71.65 r270 bottom value=100nF
C91 "Capacitor" C0402 29.55,69.9 r270 bottom value=100nF
C92 "Capacitor" C0402 29.55,71.6 r270 bottom value=100nF
C93 "Capacitor" C0402 22.775,69.925 r270 bottom value=100nF
C94 "Capacitor" C0603 52.65,63 r270 bottom value=4.7uF
C95 "Capacitor" C0402 54.925,62.85 r90 bottom value=4.7uF
C96 "Capacitor" C0402 54.05,62.85 r270 bottom value=2.2uF
C97 "Capacitor" C0402 51.625,62.675 r90 bottom value=100nF
C98 "Capacitor" C0402 48.1,62.675 r90 bottom value=100nF
C99 "Capacitor" C0402 47.2,62.675 r90 bottom value=100nF
C100 "Capacitor" C0402 57.375,60.275 r180 bottom value=1uF
C101 "Capacitor" C0402 57.375,59.475 r180 bottom value=100nF
C102 "Capacitor" C0402 59.025,58.2 r270 bottom value=3.3pF
C103 "Capacitor" C0402 40.05,57.125 r180 bottom value=100nF
C104 "Capacitor" C0402 59.05,56.2 r90 bottom value=3.3pF
C105 "Capacitor" C0603 39.725,55.625 r0 bottom value=1uF
C106 "Capacitor" C0402 40.05,52.55 r180 bottom value=100nF
C107 "Capacitor" C0402 63.05,52.525 r180 bottom value=100nF
C108 "Capacitor" C0402 40.05,50.7 r180 bottom value=100nF
C109 "Capacitor" C0402 57.1,50.1 r180 bottom value=100nF
C110 "Capacitor" C0402 27.65,59.45 r180 bottom value=100nF
C111 "Capacitor" C0402 51.525,45.825 r270 bottom value=100nF
C112 "Capacitor" C0402 49.525,45.825 r270 bottom value=100nF
C113 "Capacitor" C0402 47.025,45.825 r90 bottom value=220pF
C114 "Capacitor" C0402 44.75,45.825 r90 bottom value=10uF
C115 "Capacitor" C0402 41.7,45.825 r90 bottom value=2.2uF
C116 "Capacitor" C0402 40.825,45.825 r270 bottom value=4.7uF
C117 "Capacitor" C0402 15.575,41.325 r90 bottom value=100nF
C118 "Capacitor" C0402 9.55,41.325 r90 bottom value=100nF
C119 "Capacitor" C0402 35.125,36.05 r270 bottom value=100nF
C120 "Capacitor" C0402 25.15,14.22 r180 bottom value=330pF
C121 "" C0603 34.125,12.9 r270 bottom value=100nF
C122 "" C0402 14.425,11.97 r0 bottom value=10pF
C123 "Capacitor" C0402 27.275,10.525 r90 top value=330pF
C124 "" C0603 29.05,6.955 r270 bottom value=100nF
C125 "" C0603 43.8,6.705 r270 bottom value=100nF
C126 "Capacitor" C0603 62.85,83.825 r270 bottom value=4.7uF
C127 "Capacitor" C0402 61.025,81 r180 bottom value=100nF
C128 "Capacitor" C0402 65.27,98.45 r180 bottom value=470pF
C129 "Capacitor" C0402 58.55,93.155 r90 bottom value=470pF
CN1 "Tag-10-C" CON_TAG-C_TC2050-IDC-NL 41.8,101.015 r0 top value="Header 5x2"
CN2 "Socket 10x2" CON_FCI_20021311-XXX20XXLF 74.6,86.9 r270 top
CN3 "Socket 10X2 STMod+" CON_SAMTEC_SQT-110-01-F-D-RA__STMOD+ 8.65,80.3 r270 top value="Socket 10X2"
CN4 "DF37NB-10DS-0.4V" CON_HRS_DF37NB-10DS-04V 48.05,84.95 r90 top value=Socket_FFC/FPC_DF37NB-10DS-0.4V
CN5 "MR01A-01211" CON_MICROSD_ATOM_MR01A-01211 78,64.425 r90 top value=uSD-Card_MR01A-01211
CN6 "Socket 6X2 PMOD" CON_SAMTEC_SSW-106-02-F-D-RA__PMOD 11.32,25.57 r270 top value="Socket 6X2"
CN7 "FH26-29S-0.3SHW" CON_HRS_FH26-29S-03SHW 25.84,21.613 r180 top value=Socket_FFC/FPC_FH26W-29S-0.3SHW(60)
CN8 "RJ45_RTS-119A-12F6-GY-02" CON_RJ45_PHC_RMT-119A-12F6-GY-02 57.35,0.02 r0 top locked value=RJ45_RMT-119A-12F6-GY-02
CN9 "Jack_PJ3028B-3_4P" CON_PHONE-JACK-3P5_HY_PJ3028B 53.175,105 r270 bottom value="Jack_ Socket-Stereo_PJ-3028B-4P"
CN10 "USB_TYPE_C_Receptacle" CON_USB-TYPEC_WE_632723300011 28.3,105 r180 top value=USB_C_632723300011
CN11 "Header 4x1" CON_SAMTEC_TSW-104-07-G-S 24.55,76.95 r0 bottom
CN12 "Header 7x2" CON_STDC14_Receiver_MEDIUM_WITH_MIPI10_3D 15.05,94.918 r0 bottom value="Header 5x2"
CN13 "Socket 10x1" CON_SAMTEC_SSM-110-L-SV 22.752,53.069 r90 bottom
CN14 "Socket 8x1" CON_SAMTEC_SSM-108-L-SV 71.012,46.465 r90 bottom
CN15 "Socket 8x1" CON_SAMTEC_SSM-108-L-SV 22.752,28.685 r90 bottom
CN16 "Socket 6x1" CON_SAMTEC_SSM-106-L-SV 71.012,26.145 r90 bottom
CN17 "USB_TYPE_C_Receptacle" CON_USB-TYPEC_WE_632723300011 21.65,0.005 r0 top value=USB_C_632723300011
CN18 "Header 10x2" CON_SAMTEC_FTSH-110-01-L-DV 69.45,66.175 r270 bottom
D1 "STPS1L40M" DIO_DO216-AA 14.875,14.205 r90 top
D2 "SCHOTTKY_1A_2K" DIO_SOD523_1A_2K 41.85,77.65 r90 bottom value=BAT54KFILM
D3 "SCHOTTKY_1A_2K" DIO_SOD523_1A_2K 43.825,77.65 r90 bottom value=BAT54KFILM
D4 "SCHOTTKY_1A_2K" DIO_SOD523_1A_2K 45.75,77.65 r90 bottom value=BAT54KFILM
Designator89 "Comment" LOGO_ETIQUETTE 39.875,21.575 r0 bottom
Designator90 "Comment" MIRE_PLACE_SMD_0P8MM 70.85,95.2 r180 top
Designator90 "Comment" LOGO_ETIQUETTE 56.3,100.5 r270 top
Designator91 "Comment" MIRE_PLACE_SMD_0P8MM 4.525,94.65 r180 top
Designator92 "Comment" MIRE_PLACE_SMD_0P8MM 8.8,1.65 r0 top
Designator93 "Comment" MIRE_PLACE_SMD_0P8MM 69.2,1.5 r180 bottom
Designator94 "Comment" MIRE_PLACE_SMD_0P8MM 75.55,95.85 r0 bottom
Designator95 "Comment" MIRE_PLACE_SMD_0P8MM 4.375,94.6 r0 bottom
H1 "POSITION HOLE" PTH_M1261-3005-N_3P5X6_M3_H14 73,100 r0 bottom value=xxx
H2 "POSITION HOLE" PTH_M1261-3005-N_3P5X6_M3_H14 5,100 r0 bottom value=xxx
H3 "POSITION HOLE" PTH_M1261-3005-N_3P5X6_M3_H14 73,5 r0 bottom value=xxx
H4 "POSITION HOLE" PTH_M1261-3005-N_3P5X6_M3_H14 5,5 r0 bottom value=xxx
HW1 "Comment" LCD_DRAWING_FRIDA_FRD154BP2902-D-CTQ 48.05,84.95 r0 top locked
JP1 "Jumper_Header 2x1" CON_SAMTEC_TSW-102-07-G-S 48.715,77.472 r270 bottom value="Header 2x1"
JP2 "Jumper_Header 3x1 Fitted 1-2" CON_SAMTEC_TSW-103-07-F-S 13.3,67.25 r180 top value="Header 3x1"
JP3 "Jumper_Header 2x1" CON_SAMTEC_TSW-102-07-G-S 14.175,49.5 r180 top value="Header 2x1"
JP4 "Jumper_Header 4x2" CON_SAMTEC_TSM-104-01-X-DV 5.05,42.695 r270 top value=Jumper_Header_4x2
JP5 "Jumper_Header 2x1" CON_SAMTEC_TSW-102-07-G-S 14.255,87.725 r180 bottom value="Header 2x1"
JP6 "Jumper_Header 2x1" CON_SAMTEC_TSW-102-07-G-S 61.9,47.95 r180 bottom value="Header 2x1"
L1 "BEAD" L0603 55.85,30.175 r270 top value="600R @100MHz"
L2 "BEAD" L0603 20.225,17.425 r0 top value="600R @ 100MHz"
L3 "Inductor" L1210_LQH 9.725,15.375 r0 top value=4.7uH
L4 "Inductor" L0805_H0P9 43.15,45.25 r270 bottom value=2.2uH
L5 "Inductor" IND_0402_MURATA_BLM15H_H0P5 55.825,83.125 r0 bottom value="10R @100MHz"
L6 "Inductor" IND_0402_MURATA_BLM15H_H0P5 58.725,70.7 r90 bottom value="10R @100MHz"
L7 "Inductor" IND_0402_MURATA_BLM15H_H0P5 52.925,70.8 r90 bottom value="10R @100MHz"
L8 "Inductor" IND_0402_MURATA_BLM15H_H0P5 64.475,83.125 r180 bottom value="10R @100MHz"
L9 "Inductor" IND_0402_MURATA_BLM15H_H0P5 65.175,97.325 r180 bottom value="10R @100MHz"
L10 "Inductor" IND_0402_MURATA_BLM15H_H0P5 59.625,93.25 r90 bottom value="10R @100MHz"
LD1 "LED_green" LED_0603_OSRAM_LG-Q396-PS-35_GREEN_1A2K_H0P4 73.165,47.99 r180 top value=GREEN
LD2 "LED_orange" LED_0603_OSRAM_LO-Q976-PS-25_ORANGE_1A2K_H0P8 73.165,50.04 r180 top value=ORANGE
LD3 "LED_red" LED_0603_VISHAY_VLMS1300-GS08_RED_1A2K_H0P8 73.165,52.115 r180 top value=RED
LD4 "LED_blue" LED_0603_OSRAM_LB-Q39G-L2OO-35-1_BLUE_1A2K_H0P4 73.165,54.24 r180 top value=BLUE
LD5 "LED_green" LED_0603_VISHAY_VLMTG1300-GS08_GREEN_1A2K_H0P8 6.298,49.725 r0 top value=GREEN
LD6 "LED_green" LED_0603_OSRAM_LG-Q396-PS-35_GREEN_1A2K_H0P4 73.115,45.84 r0 top value=GREEN
LD7 "" LED_0603_OSRAM_LG-Q396-PS-35_GREEN_1A2K_H0P4 11.95,6.595 r90 top value=GREEN
LD8 "LED_BICOLOR" LED_BI-GR_WE-150141SV73110 11.925,101 r180 top value=Green/Red
LD9 "LED_BICOLOR" LED_BI-GR_WE-150141SV73110 17.86,101 r180 top value=Green/Red
Q1 "BSN20" MOS_SOT23 28.325,55.9 r180 bottom value=BSN20BK
Q2 "MOSFET_FDN304P" MOS_SOT23 13.2,41.375 r180 bottom value=FDN304P
Q3 "MOSFET_FDN304P" MOS_SOT23 7.275,41.375 r180 bottom value=FDN304P
Q4 "STL40DN3LLH5" PowerFLAT_5x6 39.9,6.63 r180 bottom
Q5 "STL40DN3LLH5" PowerFLAT_5x6 32.9,6.63 r180 bottom
Q6 "" NPN_SOT23 11.95,6.02 r180 bottom value="NPN SOT23"
R1 "Resistor" R0402 32.675,73.825 r90 bottom value=100K
R2 "Resistor" R0402 25.3,67.7 r270 bottom value=100K
R3 "Resistor" R0402 26.375,67.7 r270 bottom value=100K
R4 "Resistor" R0603 37.1,89.825 r270 top value=22R
R5 "Resistor" R0603 38.55,89.825 r270 top value=22R
R6 "Resistor" R0603 39.975,89.825 r270 top value=22R
R7 "Resistor" R0603 41.425,89.825 r270 top value=22R
R8 "Resistor" R0603 42.85,89.825 r270 top value=22R
R9 "Resistor" R0603 44.3,89.825 r270 top value=22R
R10 "Resistor" R0603 61.225,57.15 r270 top value=10K
R11 "Resistor" R0402 56.775,61.425 r180 top value=47K
R12 "Resistor" R0402 56.775,62.475 r180 top value=47K
R13 "Resistor" R0402 56.775,64.025 r180 top value=47K
R14 "Resistor" R0402 3.075,64.7 r0 top value=56K
R15 "Resistor" R0402 3.075,63.625 r180 top value=27K
R16 "Resistor" R0402 56.775,67.7 r180 top value=47K
R17 "Resistor" R0402 6.175,62.225 r0 top value=10K
R18 "Resistor" R0402 56.775,68.775 r180 top value=47K
R19 "Resistor" R0402 3.45,54.1 r270 top value=10K
R20 "Resistor" R0603 60.3,51.2 r90 top value=0R
R21 "Resistor" R0603 58.85,51.2 r270 top value=0R
R22 "Resistor" R0402 70.85,54.25 r0 top value=680R
R23 "Resistor" R0603 3.51,49.713 r0 top value=820R
R24 "Resistor" R0402 70.85,52.125 r0 top value=680R
R25 "Resistor" R0402 70.85,50.05 r0 top value=680R
R26 "Resistor" R0402 70.85,48 r0 top value=330R
R27 "Resistor" R0402 70.878,45.85 r180 top value=330R
R28 "Resistor" R0402 58.25,39.1 r270 top value=33R
R29 "Resistor" R0402 59.525,39.1 r90 top value=10K
R30 "Resistor" R0402 62.375,39.1 r90 top value=10K
R31 "Resistor" R0402 63.5,39.1 r270 top value=33R
R32 "Resistor" R0402 64.7,39.1 r90 top value=10K
R33 "Resistor" R0402 65.85,39.1 r270 top value=33R
R34 "Resistor" R0402 56.1,39.1 r90 top value=1K5
R35 "Resistor" R0402 57.175,39.1 r90 top value=10K
R36 "Resistor" R0402 68.2,41.675 r0 top value=100K
R37 "Resistor" R0402 56.2,36.025 r0 top value=33R
R38 "Resistor" R0402 65.825,34.95 r0 top value=0R
R39 "Resistor" R0402 56.2,34.95 r180 top value=10K
R40 "Resistor" R0402 65.375,31.05 r0 top value=12K1
R41 "Resistor" R0402 19.45,25.3 r0 top value=100K
R42 "Resistor" R0402 68.5,14.625 r270 top value=10K
R43 "Resistor" R0402 23.15,18.375 r270 top value=0R
R44 "Resistor" R0402 24.225,18.375 r270 top value=100K
R45 "Resistor" R0402 36.75,94.8 r180 bottom value=5K1
R46 "Resistor" R0402 36.75,95.875 r180 bottom value=100K
R47 "Resistor" R0402 34.75,95.875 r0 bottom value=100K
R48 "Resistor" R0402 34.75,94.8 r0 bottom value=5K1
R49 "Resistor" R0402 6.3,14.5 r0 top value=0R
R50 "Resistor" R0402 68.325,22.375 r270 top value=270R
R51 "Resistor" R0402 6.3,11.125 r0 top value=100K
R52 "Resistor" R0402 6.3,10.05 r0 top value=10R
R53 "Resistor" R0402 46.45,24.275 r90 top value=10K
R54 "Resistor" R0402 46.45,21.975 r270 top value=270R
R55 "Resistor" R0402 9.325,8.525 r0 top value=100K
R56 "" R0603 11.95,3.92 r270 top value=270R
R57 "Resistor" R0603 64.4,75.575 r180 bottom value=0R
R58 "Resistor" R0402 17.6,99.675 r270 bottom value=100R
R59 "Resistor" R0402 18.6,97.7 r270 top value=1K
R60 "Resistor" R0402 17.199,97.7 r90 top value=330R
R61 "Resistor" R0402 29.975,67.7 r270 bottom value=47R
R62 "Resistor" R0603 60.975,73.075 r0 bottom value=0R
R63 "Resistor" R0402 32.125,67.7 r270 bottom value=100K
R64 "Resistor" R0402 24.3,91.425 r90 bottom value=5K1
R65 "Resistor" R0402 25.35,91.425 r90 bottom value=10K
R66 "Resistor" R0402 23.225,91.425 r90 bottom value=10K
R67 "Resistor" R0402 22.15,91.425 r90 bottom value=10K
R68 "Resistor" R0402 24,94 r180 bottom value=0R
R69 "Resistor" R0402 31.05,67.7 r270 bottom value=47R
R70 "Resistor" R0402 67.116,86.994 r270 bottom value=10K
R71 "Resistor" R0402 32.45,85.35 r0 bottom value=3K
R72 "Resistor" R0402 33.2,67.7 r270 bottom value=47R
R73 "Resistor" R0603 58.65,73.075 r180 bottom value=0R
R74 "Resistor" R0402 35.125,75.975 r180 bottom value=5K1
R75 "Resistor" R0402 32.45,82.9 r0 bottom value=0R
R76 "Resistor" R0402 59.075,81.025 r0 bottom value=2K2
R77 "Resistor" R0603 64.925,94.975 r180 bottom value=20R
R78 "Resistor" R0402 34.275,67.7 r270 bottom value=47R
R79 "Resistor" R0603 61.925,93.375 r90 bottom value=20R
R80 "Resistor" R0402 63,73.1 r0 bottom value=1K5
R81 "Resistor" R0402 56.625,73.075 r180 bottom value=1K5
R82 "Resistor" R0402 24.175,73.825 r90 bottom value=100K
R83 "Resistor" R0402 26.325,73.825 r90 bottom value=100K
R84 "Resistor" R0402 25.25,73.825 r90 bottom value=100K
R85 "Resistor" R0402 18.725,81.375 r180 bottom value=10K
R86 "Resistor" R0402 35.125,79.125 r180 bottom value=1K8
R87 "Resistor" R0402 35.125,77.025 r180 bottom value=3K
R88 "Resistor" R0402 57.725,57.75 r180 bottom value=0R
R89 "Resistor" R0402 57.725,56.65 r180 bottom value=0R
R90 "Resistor" R0402 66.925,55.41 r180 bottom value=1K
R91 "Resistor" R0402 28.825,53.45 r0 bottom value=1M
R92 "Resistor" R0402 58.1,52.275 r180 bottom value=51R
R93 "Resistor" R0402 62.6,51.2 r270 bottom value=10K
R94 "Resistor" R0402 58.1,51.225 r0 bottom value=51R
R95 "Resistor" R0402 27.65,58.4 r0 bottom value=0R
R96 "Resistor" R0603 45.9,45.5 r270 bottom value=0R
R97 "Resistor" R0402 61.125,64.55 r180 bottom value=0R
R98 "Resistor" R0402 61.125,63.425 r180 bottom value=0R
R99 "Resistor" R0402 4.825,41.45 r90 bottom value=0R
R100 "Resistor" R0402 10.825,41.325 r90 bottom value=0R
R101 "Resistor" R0402 14.125,38.475 r90 bottom value=10K
R102 "Resistor" R0402 8.2,38.475 r90 bottom value=10K
R103 "Resistor" R0402 14.125,36.725 r90 bottom value=100K
R104 "Resistor" R0402 32.945,35.825 r90 bottom value=10K
R105 "Resistor" R0402 54.15,45.125 r90 bottom value=33R
R106 "Resistor" R0402 36.575,51.475 r180 bottom value=33R
R107 "Resistor" R0402 32.77,31.1 r180 bottom value=0R
R108 "Resistor" R0402 41.67,30.75 r180 bottom value=10K
R109 "Resistor" R0402 32.745,30.025 r0 bottom value=0R
R110 "Resistor" R0402 63.3,29.55 r270 top value=49R9
R111 "Resistor" R0402 62.25,29.55 r270 top value=49R9
R112 "Resistor" R0402 61.225,29.525 r270 top value=49R9
R113 "Resistor" R0402 60.125,29.525 r270 top value=49R9
R114 "Resistor" R0402 32.745,28.95 r0 bottom value=0R
R115 "Resistor" R0402 32.745,27.825 r0 bottom value=0R
R116 "Resistor" R0402 39.345,25.2 r90 bottom value=0R
R117 "Resistor" R0402 37.045,25.2 r90 bottom value=0R
R118 "Resistor" R0402 35.92,25.2 r270 bottom value=0R
R119 "Resistor" R0402 38.195,25.2 r90 bottom value=0R
R120 "Resistor" R0402 34.695,25.2 r90 bottom value=0R
R121 "Resistor" R0805_H0P5 37.875,12.575 r90 bottom value=0R047
R122 "Resistor" R0402 36.4,13.225 r90 bottom value=10K
R123 "Resistor" R0402 35.35,13.225 r270 bottom value=2K4
R124 "" R0603 14.1,10.795 r0 bottom value=49K9
R125 "" R0603 14.1,9.37 r180 bottom value=330K
R126 "" R0603 11.95,3.27 r180 bottom value=22K
R127 "" R0603 11.95,1.82 r0 bottom value=47K
R128 "Resistor" R0402 35.125,78.075 r180 bottom value=1K3
R129 "Resistor" R0402 35.125,80.175 r180 bottom value=3K9
R130 "Resistor" R0402 12.709,97.7 r270 top value=1K
R131 "Resistor" R0402 11.275,97.7 r270 top value=330R
R132 "Resistor" R0402 35.35,67.7 r90 bottom value=100K
R133 "Resistor" R0402 49.15,74.1 r180 bottom value=100K
R134 "Resistor" R0402 30.525,73.825 r270 bottom value=100K
R135 "Resistor" R0402 31.6,73.825 r90 bottom value=100K
R136 "Resistor" R0402 33.75,73.825 r90 bottom value=100K
R137 "Resistor" R0402 38.05,80.25 r0 bottom value=100K
R138 "Resistor" R0402 42.1,71.75 r0 bottom value=100K
R139 "Resistor" R0402 46.5,70.575 r180 bottom value=100K
SB1 "SB_ON" SOLDER-BRIDGE_R0603-0R 62.6,70.7 r90 bottom value=0R
SB2 "SB_ON" SOLDER-BRIDGE_R0603-0R 13.975,79.325 r180 bottom value=0R
SB3 "SB_ON" SOLDER-BRIDGE_R0603-0R 13.975,77.9 r180 bottom value=0R
SB4 "SB_ON" SOLDER-BRIDGE_R0603-0R 13.975,76.475 r180 bottom value=0R
SB5 "SB_ON" SOLDER-BRIDGE_R0603-0R 13.975,75.05 r180 bottom value=0R
SB6 "SB_ON" SOLDER-BRIDGE_R0603-0R 13.975,73.625 r180 bottom value=0R
SB7 "SB_ON" SOLDER-BRIDGE_R0603-0R 13.975,72.2 r180 bottom value=0R
SB8 "SB_ON" SOLDER-BRIDGE_R0603-0R 13.975,70.775 r180 bottom value=0R
SB9 "SB_ON" SOLDER-BRIDGE_R0603-0R 13.975,69.35 r180 bottom value=0R
SB10 "SB_ON" SOLDER-BRIDGE_R0603-0R 2.8,67.675 r90 bottom value=0R
SB11 "SB_ON" SOLDER-BRIDGE_R0603-0R 49.425,63.225 r270 bottom value=0R
SB12 "SB_ON" SOLDER-BRIDGE_R0603-0R 58.225,61.325 r180 bottom value=0R
SB13 "SB_ON" SOLDER-BRIDGE_R0603-0R 7.7,57.85 r90 bottom value=0R
SB14 "SB_ON" SOLDER-BRIDGE_R0603-0R 39.5,54.325 r0 bottom value=0R
SB15 "SB_ON" SOLDER-BRIDGE_R0603-0R 28.675,51.75 r0 bottom value=0R
SB16 "SB_ON" SOLDER-BRIDGE_R0603-0R 28.2,62.075 r0 bottom value=0R
SB17 "SB_ON" SOLDER-BRIDGE_R0603-0R 45.575,95.875 r90 top value=0R
SB18 "SB_ON" SOLDER-BRIDGE_R0603-0R 74.225,63.475 r90 bottom value=0R
SB19 "SB_ON" SOLDER-BRIDGE_R0603-0R 28.2,63.95 r0 bottom value=0R
SB20 "SB_ON" SOLDER-BRIDGE_R0603-0R 36.32,36.6 r270 bottom value=0R
SB21 "SB_ON" SOLDER-BRIDGE_R0603-0R 65.627,22.49 r0 bottom value=0R
SB22 "SB_ON" SOLDER-BRIDGE_R0603-0R 32.945,33.15 r90 bottom value=0R
SB23 "SB_ON" SOLDER-BRIDGE_R0603-0R 65.627,23.915 r0 bottom value=0R
SB24 "SB_ON" SOLDER-BRIDGE_R0603-0R 65.625,25.35 r0 bottom value=0R
SB25 "SB_ON" SOLDER-BRIDGE_R0603-0R 65.625,26.775 r0 bottom value=0R
SB28 "SB_ON" SOLDER-BRIDGE_R0603-0R 39.925,1.68 r0 bottom value=0R
SB29 "SB_ON" SOLDER-BRIDGE_R0603-0R 34.225,1.68 r0 bottom value=0R
SW1 "SW_MECA_1K2" SWI_EAO_09-03290-01_EXTENDED_STRAIGHT_BLACK 70.475,14.225 r0 top value=09.03290.01
TP2 "Test Point" TP_SMD_2MM 2.85,71.45 r270 bottom
TP3 "Test Point" TP_SMD_2MM 11.3,64.5 r180 bottom
TP4 "Test Point" TP_SMD_2MM 10.975,57.6 r270 bottom
TP5 "Test Point" TP_SMD_1MM 28.725,30.625 r270 bottom value="Test Point 1mm"
TP13 "Test Point" TP_SMD_1MM 35.28,82.775 r270 bottom value="Test Point 1mm"
U1 "ESDALC6V1W5" ESD_SOT323-5L 37.9,94.9 r0 top
U2 "ESDALC6V1W5" ESD_SOT323-5L 42.15,94.9 r0 top
U3 "ESDALC6V1W5" ESD_SOT323-5L 15.475,93.075 r90 top
U4 "ESDALC6V1W5" ESD_SOT323-5L 21.75,92.65 r270 top
U5 "HSP051-4M10" ESD_UQFN-10L_2P5X1_P050 59.275,63 r270 top
U6 "ST1L05BPUR" ICC_DFN6-EPAD_3X3_P095 5.875,64.7 r90 top
U7 "HSP051-4M10" ESD_UQFN-10L_2P5X1_P050 59.275,67.25 r270 top
U8 "LD1117S50TR" REG_SOT223-TAB 13.675,58.85 r0 top
U9 "ST1L05CPU33R" ICC_DFN6-EPAD_3X3_P095 5.875,54.35 r0 top
U10 "ESD-TRANSIL" ESD_ST0201 68.325,40.725 r180 top value=ESDALC6V1-1U2
U11 "LAN8742A-CZ-TR" ICC_VQFN24-EPAD_4X4_P050 61.625,34.2 r180 top
U12 "USBLC6-4SC6" ESD_SOT23-6L 61.125,25.67 r180 bottom
U13 "ESD-TRANSIL" ESD_QFN1610_2N_1K_2A 33.475,92.325 r270 top value=ESDA25P35-1U1M
U14 "ESD-TRANSIL" ESD_ST0201 68.575,26.1 r270 top value=ESDALC6V1-1U2
U15 "STLD40DPUR" ICC_QFN8-EPAD_3X3_P065 9.325,11.15 r270 top
U16 "ESDALC6V1W5" ESD_SOT323-5L 63.525,62.275 r90 bottom
U17 "ESD-TRANSIL" ESD_ST0201 64.45,65.525 r180 bottom value=ESDALC6V1-1U2
U18 "ESDA6V1BC6" ESD_SOT23-6L 60.6,96.9 r0 bottom
U19 "ECMF02-2AMX6" ESD_QFN-6L_1P7X1P5_P050 28.05,92 r180 top
U20 "MP23DB01MMTR" MIC_STM_MP23DB01MMTR 71.445,77.4 r270 bottom value=MP23DB01HPTR
U21 "STMPS2151STR" MOS_SOT23-5L 43.675,69.325 r90 bottom
U22 "STLINK-V3EC" ICC_UFBGA201_176+25_10X10_P065 25.225,84.525 r0 bottom value=STM32F723IEK6
U23 "STG3692QTR" ICC_UFQFN16-EPAD_2P6X1P8_P040 69.216,86.994 r270 bottom
U24 "ST730M33R" ICC_SOT23-5L_H1P45 42.875,84.375 r0 bottom
U25 "WM8904CGEFL/RV" ICC_QFN32-EPAD_4X4_P040 59,77.25 r180 bottom
U26 "74AVC4TD245BQ" ICC_DHVQFN16-EPAD_SOT763-1_2P5X3P5_H0P85_P050 32.3,70.775 r270 bottom value=74AVC4TD245BQ,115
U27 "74AVC4TD245BQ" ICC_DHVQFN16-EPAD_SOT763-1_2P5X3P5_H0P85_P050 25.55,70.775 r270 bottom value=74AVC4TD245BQ,115
U28 "STM32H573IIK3Q" ICC_UFBGA201_176+25_10X10_P065 49.5,54.5 r180 bottom
U29 "MX25LM51245GXDI00" ICC_BGA24_5X5-BALL-ARRAY_6X8_P1 37.32,30.65 r180 bottom
U30 "TCPP03-M20" ICC_QFN20-EPAD_4X4_P050 35.575,17.625 r270 bottom
U31 "USBLC6-2SC6" ESD_SOT23-6L 21.6,15.1 r180 bottom
U32 "" ESD_QFN1610_2N_1K_2A 25.3,11.875 r0 bottom value=ESDA25P35-1U1M
U34 "TPS259535DSG" ICC_WSON8-EPAD_2X2_P050 37.625,77.55 r180 bottom
X1 "XTAL_4_PINS" CRY_NX2016SA_4P 15.9,84.5 r90 bottom value=24MHz
X2 "XTAL_2_PINS" CRY_NX1610SE_2P 60.25,57.2 r90 bottom value=32.768kHz
X3 "OSCILLATOR_4_PINS" OSC_NDK_NZ2520SB_4P 60.5,51.7 r180 bottom value=25MHz

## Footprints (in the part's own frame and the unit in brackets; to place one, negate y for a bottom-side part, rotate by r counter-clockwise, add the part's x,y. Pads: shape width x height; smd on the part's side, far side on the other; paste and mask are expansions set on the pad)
C0402 [mm]
  rect 0.51x0.56 smd mask+0.05: 1(-0.45,0) 2(0.45,0)
  silkscreen extent 0,-0.3 0,0.3, body extent -0.5,-0.3 0.5,0.3, height 0.4
C0603 [mm]
  rect 0.64x0.89 smd mask+0.05: 1(-0.7,0) 2(0.7,0)
  silkscreen extent -1.05,-0.55 1.02,0.55, body extent -0.9,-0.5 0.9,0.5, height 1.4
C0603_H0P8 [mm] "MCD-01540"
  rect 0.64x0.89 smd mask+0.05: 1(-0.7,0) 2(0.7,0)
  silkscreen extent -0.9,-0.55 0.9,0.55, body extent -0.9,-0.5 0.9,0.5, height 1
C0805 [mm]
  rect 0.9x1.4 smd mask+0.05: 1(-0.85,0) 2(0.85,0)
  silkscreen extent -1.3,-0.77 1.3,0.77, body extent -1.1,-0.7 1.1,0.7, height 1.35
C1206_H1P25 [mm]
  rect 1.4x1.78 smd mask+0.05: 1(-1.4,0) 2(1.4,0)
  silkscreen extent -2.12,-0.97 2.15,0.97, body extent -1.7,-0.9 1.7,0.9, height 1.45
CON_FCI_20021311-XXX20XXLF [mm]
  rect 1x1 / inner round 1 / far side rect 1x1 hole 0.7 mask+0.05: 1(5.715,0.635)
  round 1 hole 0.7 mask+0.05: 2(5.715,-0.635) 3(4.445,0.635) 4(4.445,-0.635) 5(3.175,0.635) 6(3.175,-0.635) 7(1.905,0.635) 8(1.905,-0.635) 9(0.635,0.635) 10(0.635,-0.635) 11(-0.635,0.635) 12(-0.635,-0.635) 13(-1.905,0.635) 14(-1.905,-0.635) 15(-3.175,0.635) 16(-3.175,-0.635) 17(-4.445,0.635) 18(-4.445,-0.635) 19(-5.715,0.635) 20(-5.715,-0.635)
  silkscreen extent -6.58,-1.5 6.58,1.5, body extent -6.58,-1.5 6.58,1.5, height 4.4
CON_HRS_DF37NB-10DS-04V [mm]
  rect 0.2x0.63 smd mask+0.05: 1(0.8,-1.325) 2(0.4,-1.325) 3(0,-1.325) 4(-0.4,-1.325) 5(-0.8,-1.325) 6(-0.8,1.325) 7(-0.4,1.325) 8(0,1.325) 9(0.4,1.325) 10(0.8,1.325)
  rect 0.38x1.1 smd mask+0.05: MT1(-2.04,0) MT2(2.04,0)
  silkscreen extent -2.26,-1.26 2.26,1.26, body extent -2.32,-1.32 2.32,1.32, height 1.06
CON_HRS_FH26-29S-03SHW [mm]
  rect 0.3x0.8 smd mask+0.05: 1(-4.2,-1.437) 3(-3.6,-1.437) 5(-3,-1.437) 7(-2.4,-1.437) 9(-1.8,-1.437) 11(-1.2,-1.437) 13(-0.6,-1.437) 15(0,-1.437) 17(0.6,-1.437) 19(1.2,-1.437) 21(1.8,-1.437) 23(2.4,-1.437) 25(3,-1.437) 27(3.6,-1.437) 29(4.2,-1.437)
  rect 0.3x0.65 smd mask+0.05: 2(-3.9,1.438) 4(-3.3,1.438) 6(-2.7,1.438) 8(-2.1,1.438) 10(-1.5,1.438) 12(-0.9,1.438) 14(-0.3,1.438) 16(0.3,1.438) 18(0.9,1.438) 20(1.5,1.438) 22(2.1,1.438) 24(2.7,1.438) 26(3.3,1.438) 28(3.9,1.438)
  rect 0.4x0.95 smd mask+0.05: MT1(-4.9,-1.162) MT2(4.9,-1.162)
  silkscreen extent -5.1,-1.99 5.1,1.31, body extent -5.16,-2.05 5.16,1.55, height 1
CON_MICROSD_ATOM_MR01A-01211 [mm]
  rect 0.7x1.6 smd paste+0 mask+0.05: 1(2.25,14.5) 2(1.15,14.5) 3(0.05,14.5) 4(-1.05,14.5) 5(-2.15,14.5) 6(-3.25,14.5) 7(-4.35,14.5) 8(-5.45,14.5) 9(-6.55,14.5)
  rect 1.2x1.6 smd paste+0 mask+0.05: 10(-7.75,13.9)
  rect 1.2x2.2 smd paste+0 mask+0.05: 11(-7.75,4.4) 12(7.75,4.4)
  rect 1.6x1.4 smd paste+0 mask+0.05: 13(6.85,14)
  round 0.5 hole 1 unplated paste-2539.97 mask+0.05: NPTH1(-4.95,4) NPTH2(3.05,4)
  Top Layer pour cut-out: -6.1,10.1 2.9,10.1 2.9,8.1 -6.1,8.1
  Top Layer pour cut-out: -8.35,8.1 -8.35,12.9 -6.9,12.9 -6.9,8.1
  Top Layer keep-out region: -6.1,10.1 2.9,10.1 2.9,8.1 -6.1,8.1
  Top Layer keep-out region: -8.35,8.1 -8.35,12.9 -6.9,12.9 -6.9,8.1
  silkscreen extent -7.35,-5.3 7.35,14.5, body extent -8.05,0 8.05,15, height 1.9
CON_PHONE-JACK-3P5_HY_PJ3028B [mm]
  rect 1.5x2.5 smd mask+0.05: 2(1.25,-3.45) 7(2.85,3.45)
  rect 2x2.5 smd mask+0.05: 3(4,-3.45) 4(5.8,3.45) 6(13.2,-3.45)
  rect 2.5x2 smd mask+0.05: 5(17.25,0.75)
  round 0.5 hole 2 unplated mask+0.1: MT1(5,0) MT2(12,0)
  Multi-Layer keep-out circle w0.01: c5,0 r1.25
  Multi-Layer keep-out circle w0.01: c12,0 r1.25
  silkscreen extent -0.9,-3.7 16,3, body extent -0.9,-3 16,3, height 5
CON_RJ45_PHC_RMT-119A-12F6-GY-02 [mm] "MCD-02475"
  rect 0.81x4.6 smd mask+0.05: 1(6.61,25.2) 2(4.77,25.2) 11(-4.77,25.2) 12(-6.61,25.2)
  rect 0.61x4.6 smd mask+0.05: 3(3.57,25.2) 4(2.55,25.2) 5(1.53,25.2) 6(0.51,25.2) 7(-0.51,25.2) 8(-1.53,25.2) 9(-2.55,25.2) 10(-3.57,25.2)
  rect 2.5x3.9 smd mask+0.05: 13(-8.67,5.28) 14(8.67,5.28)
  round 3.9 hole 3.25 mask+0.05: 13(-6.35,5.28) 14(6.35,5.28)
  silkscreen extent -8.9,-0.01 8.9,25.65, body extent -9.5,0 9.5,25.65, height 13.61
CON_SAMTEC_FTSH-110-01-L-DV [mm]
  rect 0.74x2.79 smd mask+0.05: 1(-5.715,-2.035) 2(-5.715,2.035) 3(-4.445,-2.035) 4(-4.445,2.035) 5(-3.175,-2.035) 6(-3.175,2.035) 7(-1.905,-2.035) 8(-1.905,2.035) 9(-0.635,-2.035) 10(-0.635,2.035) 11(0.635,-2.035) 12(0.635,2.035) 13(1.905,-2.035) 14(1.905,2.035) 15(3.175,-2.035) 16(3.175,2.035) 17(4.445,-2.035) 18(4.445,2.035) 19(5.715,-2.035) 20(5.715,2.035)
  silkscreen extent -6.35,-1.71 6.35,1.71, body extent -6.35,-2.92 6.35,2.92, height 5.97
CON_SAMTEC_SQT-110-01-F-D-RA__STMOD+ [mm] "SQT-110-01-F-D-RA (connecteur SAMTEC pour interface STMod+ femelle coté Host) Pinning adapté non conforme SAMTEC."
  rect 1.7x1.7 hole 0.9 mask+0.05: 1(9,1)
  round 1.7 hole 0.9 mask+0.05: 2(7,1) 3(5,1) 4(3,1) 5(1,1) 6(-1,1) 7(-3,1) 8(-5,1) 9(-7,1) 10(-9,1) 11(9,-1) 12(7,-1) 13(5,-1) 14(3,-1) 15(1,-1) 16(-1,-1) 17(-3,-1) 18(-5,-1) 19(-7,-1) 20(-9,-1)
  silkscreen extent -10.15,-8.62 10.15,0.07, body extent -10.15,-8.65 10.15,1.22, height 4
CON_SAMTEC_SSM-106-L-SV [mm] "MCD-02346"
  rect 1.02x1.905 smd mask+0.05: 1(-6.35,-1.602) 2(-3.81,1.603) 3(-1.27,-1.602) 4(1.27,1.603) 5(3.81,-1.602) 6(6.35,1.603)
  silkscreen extent -7.62,-1.27 7.62,1.27, body extent -7.62,-2.29 7.62,2.29, height 7.37
CON_SAMTEC_SSM-108-L-SV [mm] "MCD-02345"
  rect 1.02x1.905 smd mask+0.05: 1(-8.89,-1.602) 2(-6.35,1.603) 3(-3.81,-1.602) 4(-1.27,1.603) 5(1.27,-1.602) 6(3.81,1.603) 7(6.35,-1.602) 8(8.89,1.603)
  silkscreen extent -10.16,-1.27 10.16,1.27, body extent -10.16,-2.29 10.16,2.29, height 7.37
CON_SAMTEC_SSM-110-L-SV [mm] "MCD-02342"
  rect 1.02x1.905 smd mask+0.05: 1(-11.43,-1.602) 2(-8.89,1.603) 3(-6.35,-1.602) 4(-3.81,1.603) 5(-1.27,-1.602) 6(1.27,1.603) 7(3.81,-1.602) 8(6.35,1.603) 9(8.89,-1.602) 10(11.43,1.603)
  silkscreen extent -12.7,-1.27 12.7,1.27, body extent -12.7,-2.29 12.7,2.29, height 7.49
CON_SAMTEC_SSW-106-02-F-D-RA__PMOD [mm] "SSW-106-02-F-D-RA (connecteur SAMTEC pour interface PMOD femelle coté Host) Pinning adapté non conforme SAMTEC."
  rect 1.9x1.9 hole 1.1 mask+0.05: 1(6.35,1.27)
  round 1.9 hole 1.1 mask+0.05: 2(3.81,1.27) 3(1.27,1.27) 4(-1.27,1.27) 5(-3.81,1.27) 6(-6.35,1.27) 7(6.35,-1.27) 8(3.81,-1.27) 9(1.27,-1.27) 10(-1.27,-1.27) 11(-3.81,-1.27) 12(-6.35,-1.27)
  silkscreen extent -7.88,-11.3 7.88,0.23, body extent -7.87,-11.31 7.87,1.47, height 5.21
CON_SAMTEC_TSM-104-01-X-DV [mm]
  rect 1.3x2.9 smd paste+0 mask+0.05: 1(-3.81,-2.55) 2(-3.81,2.55) 3(-1.27,-2.55) 4(-1.27,2.55) 5(1.27,-2.55) 6(1.27,2.55) 7(3.81,-2.55) 8(3.81,2.55)
  silkscreen extent -5.24,-2.22 5.24,2.22, body extent -5.24,-3.85 5.24,3.85, height 9.65
CON_SAMTEC_TSW-102-07-G-S [mm]
  rect 1.85x1.85 / inner round 1.85 / far side rect 1.85x1.85 hole 1 mask+0.05: 1(-1.27,0)
  round 1.85 hole 1 mask+0.05: 2(1.27,0)
  silkscreen extent -2.58,-1.3 2.58,1.3, body extent -2.67,-1.3 2.58,1.3, height 8.38
CON_SAMTEC_TSW-103-07-F-S [mm]
  rect 1.85x1.85 / inner round 1.85 / far side rect 1.85x1.85 hole 1 mask+0.05: 1(-2.54,0)
  round 1.85 hole 1 mask+0.05: 2(0,0) 3(2.54,0)
  silkscreen extent -3.85,-1.3 3.85,1.3, body extent -3.94,-1.37 3.91,1.37, height 8.38
CON_SAMTEC_TSW-104-07-G-S [mm]
  rect 1.85x1.85 / inner round 1.85 / far side rect 1.85x1.85 hole 1 mask+0.05: 1(-3.81,0)
  round 1.85 hole 1 mask+0.05: 2(-1.27,0) 3(1.27,0) 4(3.81,0)
  silkscreen extent -5.12,-1.3 5.12,1.3, body extent -5.21,-1.37 5.18,1.37, height 8.38
CON_STDC14_Receiver_MEDIUM_WITH_MIPI10_3D [mm] "compatible with FTSH-105-01-L-DV,-K and FTSH-107-01-L-DV,-K,-A,-P,-ES"
  round 0 hole 1.19 unplated mask+0.05: 0(-5.445,0) 0(5.445,0)
  round 0 hole 0.97 unplated mask+0.05: 0(-3.175,0) 0(3.175,0)
  rect 0.74x2.79 smd mask+0.05: 1(-3.81,-2.032) 2(-3.81,2.032) 3(-2.54,-2.032) 4(-2.54,2.032) 5(-1.27,-2.032) 6(-1.27,2.032) 7(0,-2.032) 8(0,2.032) 9(1.27,-2.032) 10(1.27,2.032) 11(2.54,-2.032) 12(2.54,2.032) 13(3.81,-2.032) 14(3.81,2.032)
  silkscreen extent -6.3,-4.38 6.3,3.6, body extent -6.3,-2.92 6.3,2.92, height 6.6
CON_TAG-C_TC2050-IDC-NL [mm]
  round 0.9 smd paste+0 mask+0.05: 1(-2.54,-0.635) 2(-1.27,-0.635) 3(0,-0.635) 4(1.27,-0.635) 5(2.54,-0.635) 6(2.54,0.635) 7(1.27,0.635) 8(0,0.635) 9(-1.27,0.635) 10(-2.54,0.635)
  round 0 hole 1.1 unplated mask+0.05: 11(-3.81,0) 12(3.81,-1.015) 13(3.81,1.015)
  Multi-Layer keep-out circle w0.01: c-3.81,0 r0.75
  Multi-Layer keep-out circle w0.01: c3.81,1.015 r0.75
  Multi-Layer keep-out circle w0.01: c3.81,-1.015 r0.75
  silkscreen extent -6.22,-3.4 6.22,3.33, body extent -6.28,-3.46 6.28,3.39, height 13
CON_USB-TYPEC_WE_632723300011 [mm]
  rect 0.3x1.2 smd mask+0.05: A1(-2.75,10.58) A2(-2.25,10.58) A3(-1.75,10.58) A4(-1.25,10.58) A5(-0.75,10.58) A6(-0.25,10.58) A7(0.25,10.58) A8(0.75,10.58) A9(1.25,10.58) A10(1.75,10.58) A11(2.25,10.58) A12(2.75,10.58)
  round 0.6 hole 0.4 mask+0.05: B1(2,9.33) B1(2.8,9.33) B2(2.4,8.62) B3(1.6,8.62) B4(1.2,9.33) B5(0.8,8.62) B6(0.4,9.33) B7(-0.4,9.33) B8(-0.8,8.62) B9(-1.2,9.33) B10(-1.6,8.62) B11(-2.4,8.62) B12(-2.8,9.33) B12(-2,9.33)
  oval 1.15x1.55 hole 0.45 slot 0.85 at 90 deg mask+0.05: SH1(-4.27,8.18) SH2(-4.27,3.45) SH3(4.27,8.18) SH4(4.27,3.45)
  silkscreen extent -4.38,-0.95 4.38,10.38, body extent -4.38,-0.98 4.38,10.82, height 3.03
CRY_NX1610SE_2P [mm] "MCD-02291"
  rect 0.5x1 smd mask+0.05: 1(-0.55,0) 2(0.55,0)
  silkscreen extent -0.13,-0.5 0.13,0.5, body extent -0.8,-0.5 0.8,0.5, height 0.45
CRY_NX2016SA_4P [mm]
  rect 0.85x0.75 smd mask+0.05: 1(-0.675,-0.525) 2(0.675,-0.525) 3(0.675,0.525) 4(-0.675,0.525)
  silkscreen extent -1.22,-1.02 1.05,0.85, body extent -1.05,-0.85 1.05,0.85, height 0.7
DIO_DO216-AA [mm]
  rect 1.38x0.75 smd mask+0.05: 1(1.515,0)
  rect 2.32x1.1 smd mask+0.05: 2(-1.045,0)
  Top Layer region: -1.705,-1.015 0.115,-1.015 0.115,1.015 -1.705,1.015
  silkscreen extent -2.25,-1.22 0.72,1.22, body extent -2.02,-1.02 1.83,1.02, height 1.15
DIO_SOD523_1A_2K [mm] "MCD-01677"
  rect 0.65x0.3 smd mask+0.05: 1(-0.675,0) 2(0.675,0)
  silkscreen extent -0.65,-0.45 1.05,0.55, body extent -0.85,-0.45 0.85,0.45, height 0.71
ESD_QFN1610_2N_1K_2A [mm] "DFN, 2-Leads, Body 1.60x1.00mm"
  rect 0.55x0.9 smd mask+0.05: 1(-0.625,0) 2(0.625,0)
  silkscreen extent -1.02,-0.58 0.85,0.58, body extent -0.85,-0.55 0.85,0.55, height 0.6
ESD_QFN-6L_1P7X1P5_P050 [mm]
  rect 0.25x0.6 smd mask+0.05: 1(-0.5,-0.65) 2(0,-0.65) 3(0.5,-0.65) 4(0.5,0.65) 5(0,0.65) 6(-0.5,0.65)
  silkscreen extent -0.9,-0.8 0.9,0.8, body extent -0.9,-0.8 0.9,0.8, height 0.56
ESD_SOT23-6L [mm]
  rect 0.6x1.2 smd mask+0.05: 1(-0.95,-1.15) 2(0,-1.15) 3(0.95,-1.15) 4(0.95,1.15) 5(0,1.15) 6(-0.95,1.15)
  silkscreen extent -1.53,-0.87 1.53,0.87, body extent -1.52,-1.5 1.52,1.5, height 1.45
ESD_SOT323-5L [mm]
  rect 0.4x1.2 smd mask+0.05: 1(-0.65,-0.85) 2(0,-0.85) 3(0.65,-0.85) 4(0.65,0.85) 5(-0.65,0.85)
  silkscreen extent -1.22,-1.21 1.22,0.77, body extent -1.15,-1.05 1.15,1.05, height 1.1
ESD_ST0201 [mm]
  rect 0.425x0.33 smd mask+0.05: 1(-0.312,0) 2(0.312,0)
  silkscreen extent -0.55,-0.3 0.33,0.3, body extent -0.34,-0.18 0.34,0.18, height 0.34
ESD_UQFN-10L_2P5X1_P050 [mm]
  rect 0.2x0.58 smd mask+0.05: 1(-1,-0.41) 2(-0.5,-0.41) 4(0.5,-0.41) 5(1,-0.41) 6(1,0.41) 7(0.5,0.41) 9(-0.5,0.41) 10(-1,0.41)
  rect 0.4x0.58 smd mask+0.05: 3(0,-0.41) 8(0,0.41)
  silkscreen extent -1.38,-0.63 1.38,0.63, body extent -1.3,-0.55 1.3,0.55, height 0.51
ICC_BGA24_5X5-BALL-ARRAY_6X8_P1 [mm]
  round 0.45 smd mask+0.05: A2(-1,2) A3(0,2) A4(1,2) A5(2,2) B1(-2,1) B2(-1,1) B3(0,1) B4(1,1) B5(2,1) C1(-2,0) C2(-1,0) C3(0,0) C4(1,0) C5(2,0) D1(-2,-1) D2(-1,-1) D3(0,-1) D4(1,-1) D5(2,-1) E1(-2,-2) E2(-1,-2) E3(0,-2) E4(1,-2) E5(2,-2)
  silkscreen extent -3.05,-4.05 3.05,4.05, body extent -3.05,-4.05 3.05,4.05, height 1.2
ICC_DFN6-EPAD_3X3_P095 [mm]
  rect 0.45x0.5 smd mask+0.05: 1(-0.95,-1.3) 2(0,-1.3) 3(0.95,-1.3) 4(0.95,1.3) 5(0,1.3) 6(-0.95,1.3)
  rect 2.5x1.7 smd mask+0.05: EP(0,0)
  silkscreen extent -1.55,-1.55 1.55,1.55, body extent -1.55,-1.55 1.55,1.55, height 1
ICC_DHVQFN16-EPAD_SOT763-1_2P5X3P5_H0P85_P050 [mm] "MCD-01945"
  rect 0.3x0.8 smd mask+0.05: 1(-0.25,1.7) 8(-0.25,-1.7) 9(0.25,-1.7) 16(0.25,1.7)
  rect 0.8x0.3 smd mask+0.05: 2(-1.2,1.25) 3(-1.2,0.75) 4(-1.2,0.25) 5(-1.2,-0.25) 6(-1.2,-0.75) 7(-1.2,-1.25) 10(1.2,-1.25) 11(1.2,-0.75) 12(1.2,-0.25) 13(1.2,0.25) 14(1.2,0.75) 15(1.2,1.25)
  rect 1.2x2.2 smd mask+0.05: 17(0,0)
  silkscreen extent -1.3,-1.8 1.3,1.8, body extent -1.31,-1.81 1.31,1.81, height 1.01
ICC_QFN8-EPAD_3X3_P065 [mm]
  rect 0.4x0.6 smd paste+0 mask+0.05: 1(-0.975,-1.4) 2(-0.325,-1.4) 3(0.325,-1.4) 4(0.975,-1.4) 5(0.975,1.4) 6(0.325,1.4) 7(-0.325,1.4) 8(-0.975,1.4)
  rect 3.6x1.9 smd paste+0 mask+0: 9(0,0)
  silkscreen extent -1.58,-1.58 1.58,1.58, body extent -1.58,-1.58 1.58,1.58, height 1
ICC_QFN20-EPAD_4X4_P050 [mm] "MCD-02130"
  rect 0.75x0.3 smd mask+0.05: 1(-1.925,1) 2(-1.925,0.5) 3(-1.925,0) 4(-1.925,-0.5) 5(-1.925,-1) 11(1.925,-1) 12(1.925,-0.5) 13(1.925,0) 14(1.925,0.5) 15(1.925,1)
  rect 0.3x0.75 smd mask+0.05: 6(-1,-1.925) 7(-0.5,-1.925) 8(0,-1.925) 9(0.5,-1.925) 10(1,-1.925) 16(1,1.925) 17(0.5,1.925) 18(0,1.925) 19(-0.5,1.925) 20(-1,1.925)
  rect 2.7x2.7 smd mask+0.05: 21(0,0)
  silkscreen extent -2.07,-2.07 2.07,2.07, body extent -2.13,-2.13 2.13,2.13, height 1.01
